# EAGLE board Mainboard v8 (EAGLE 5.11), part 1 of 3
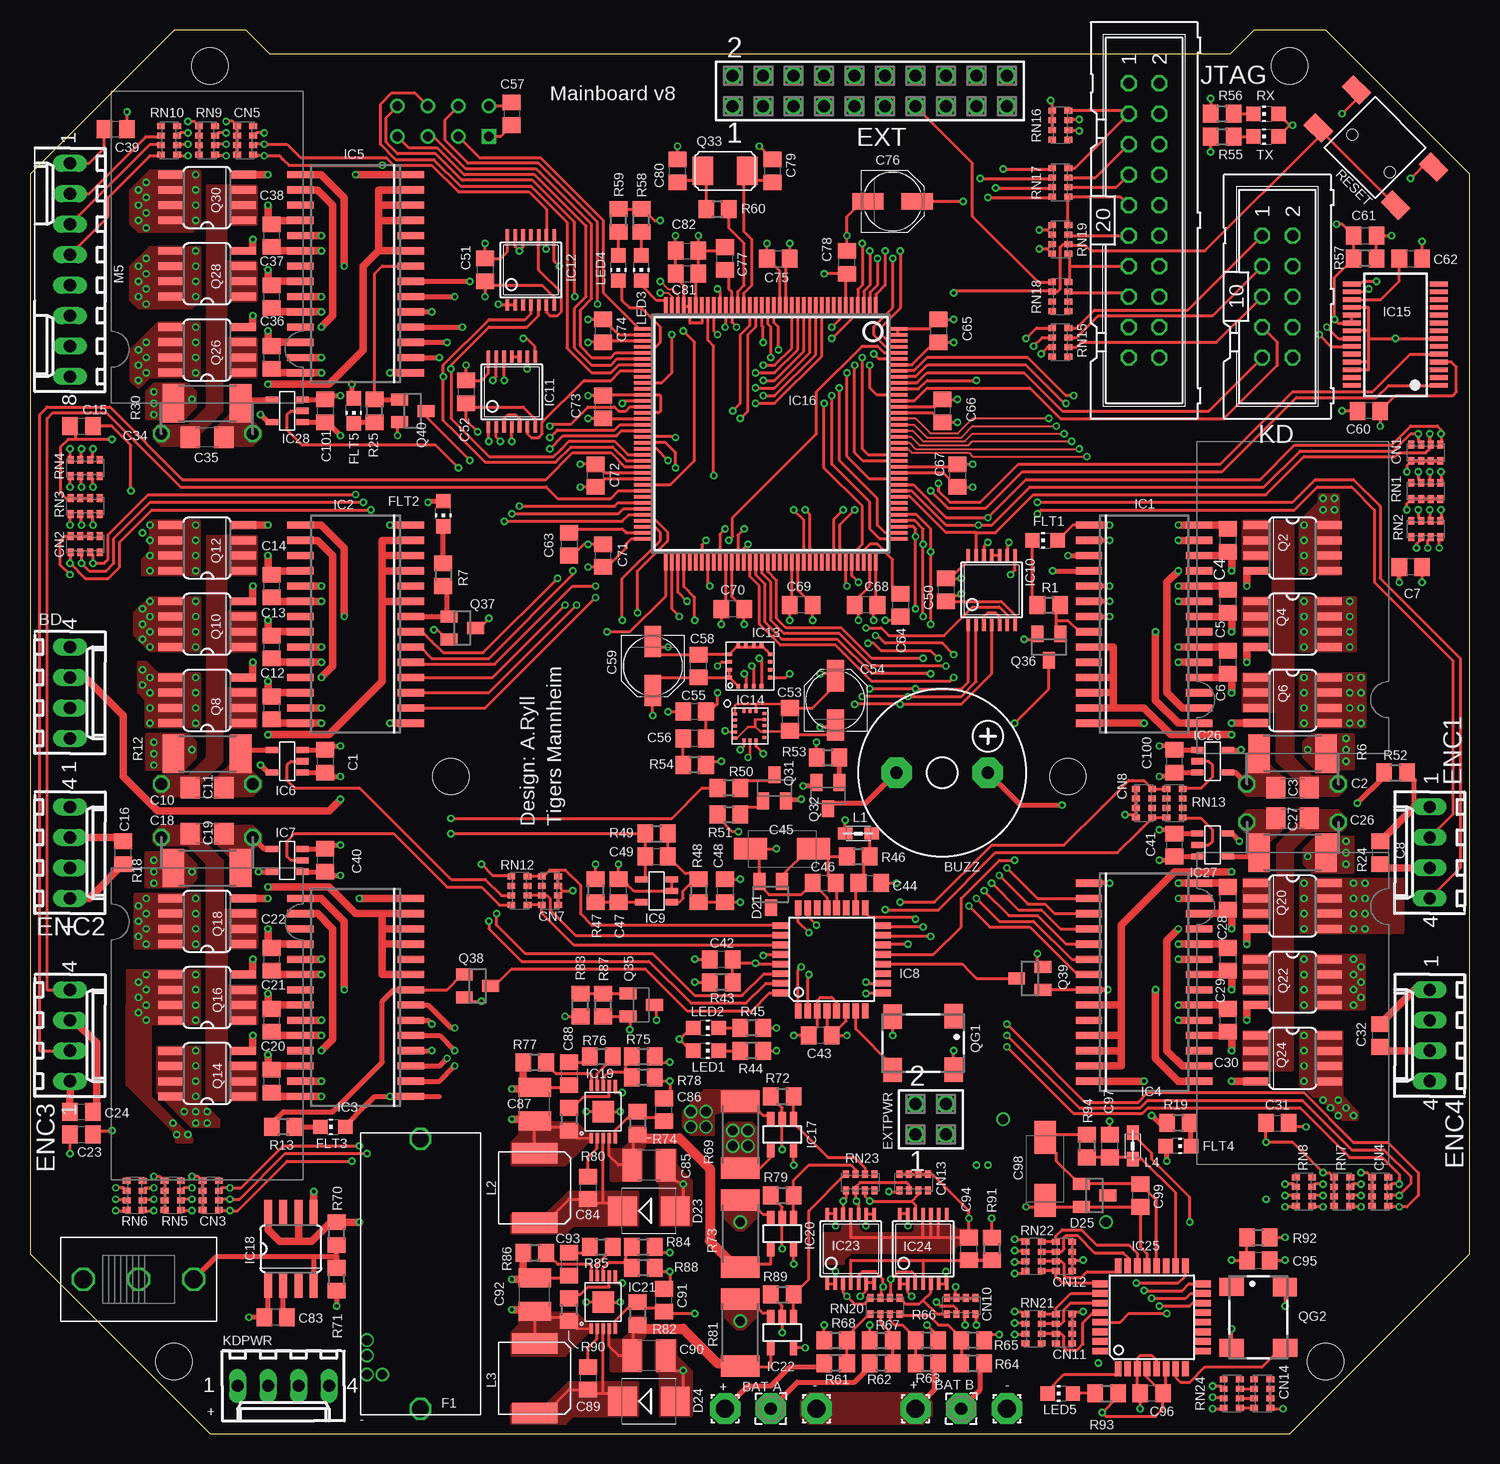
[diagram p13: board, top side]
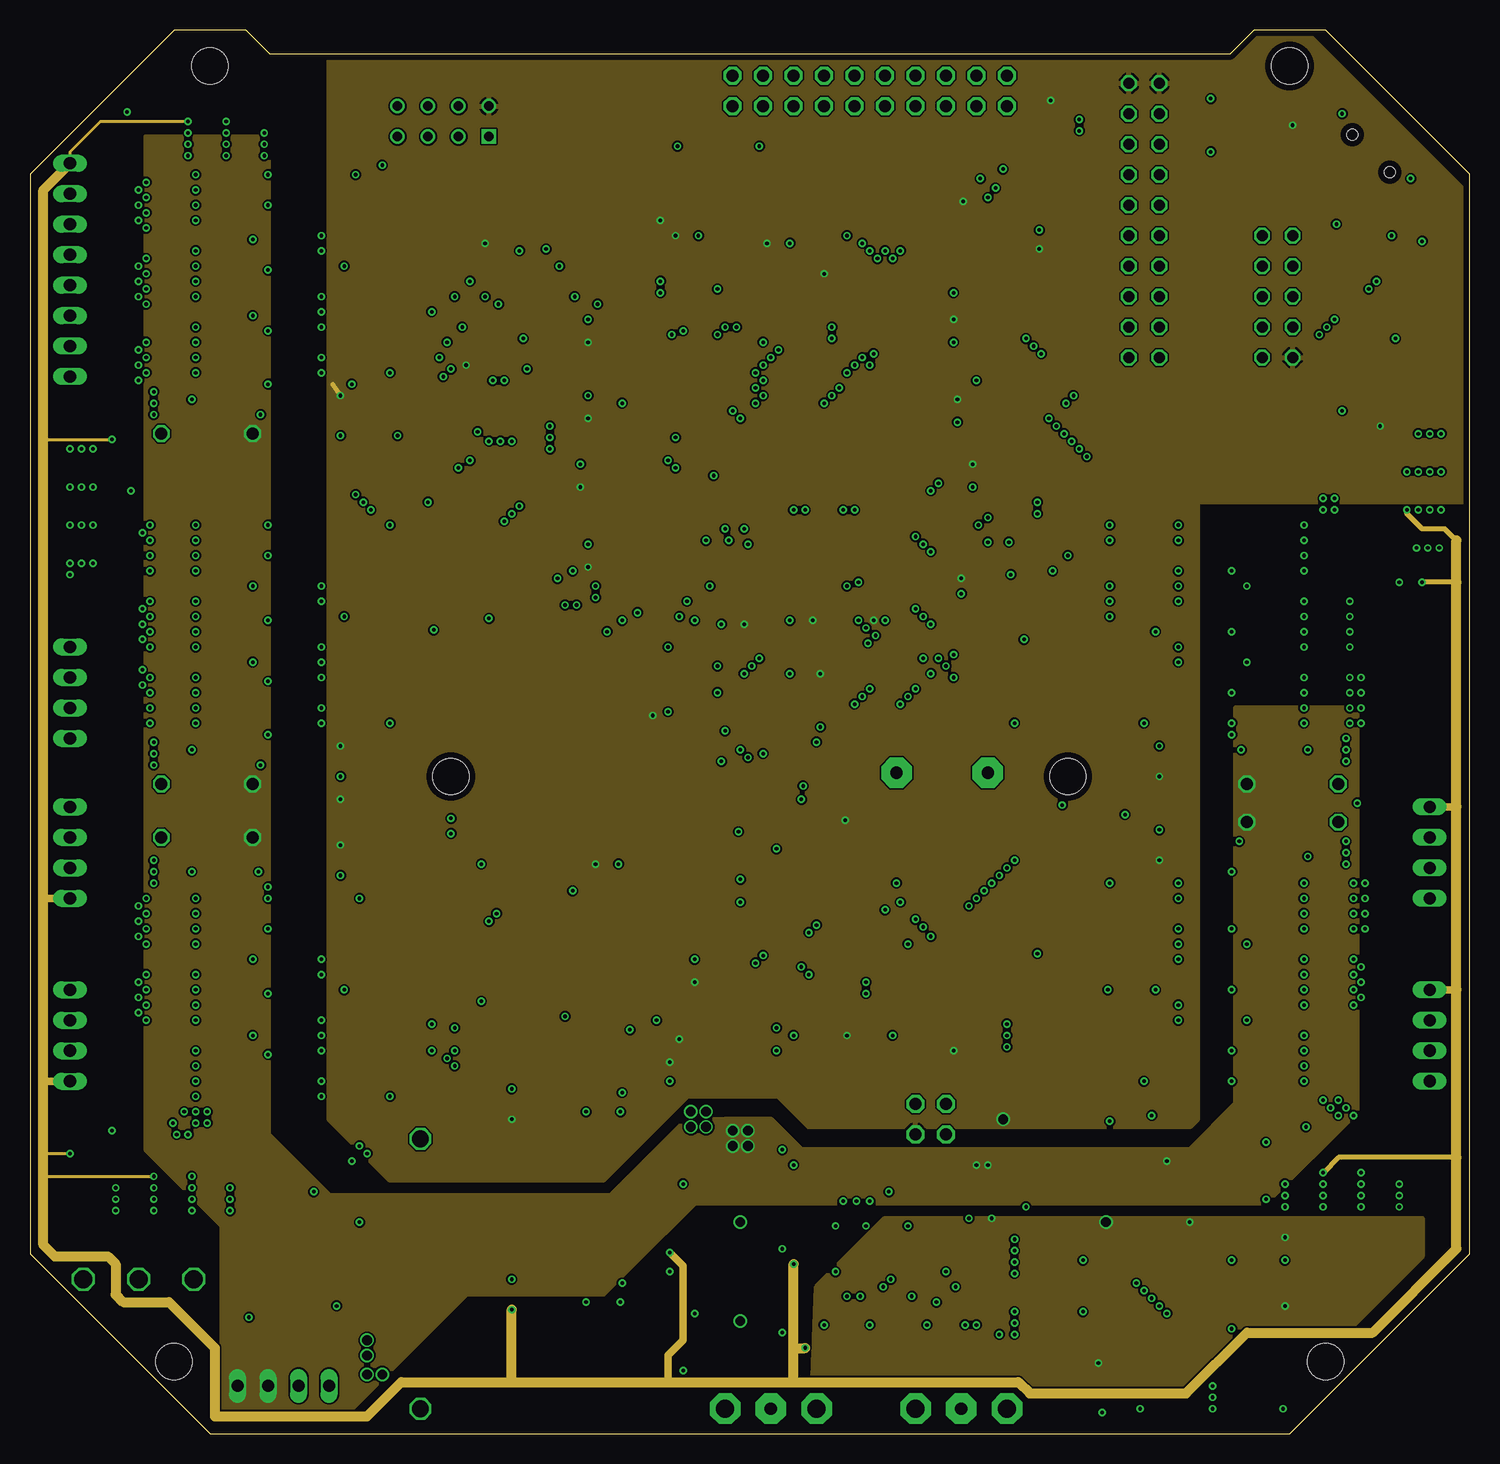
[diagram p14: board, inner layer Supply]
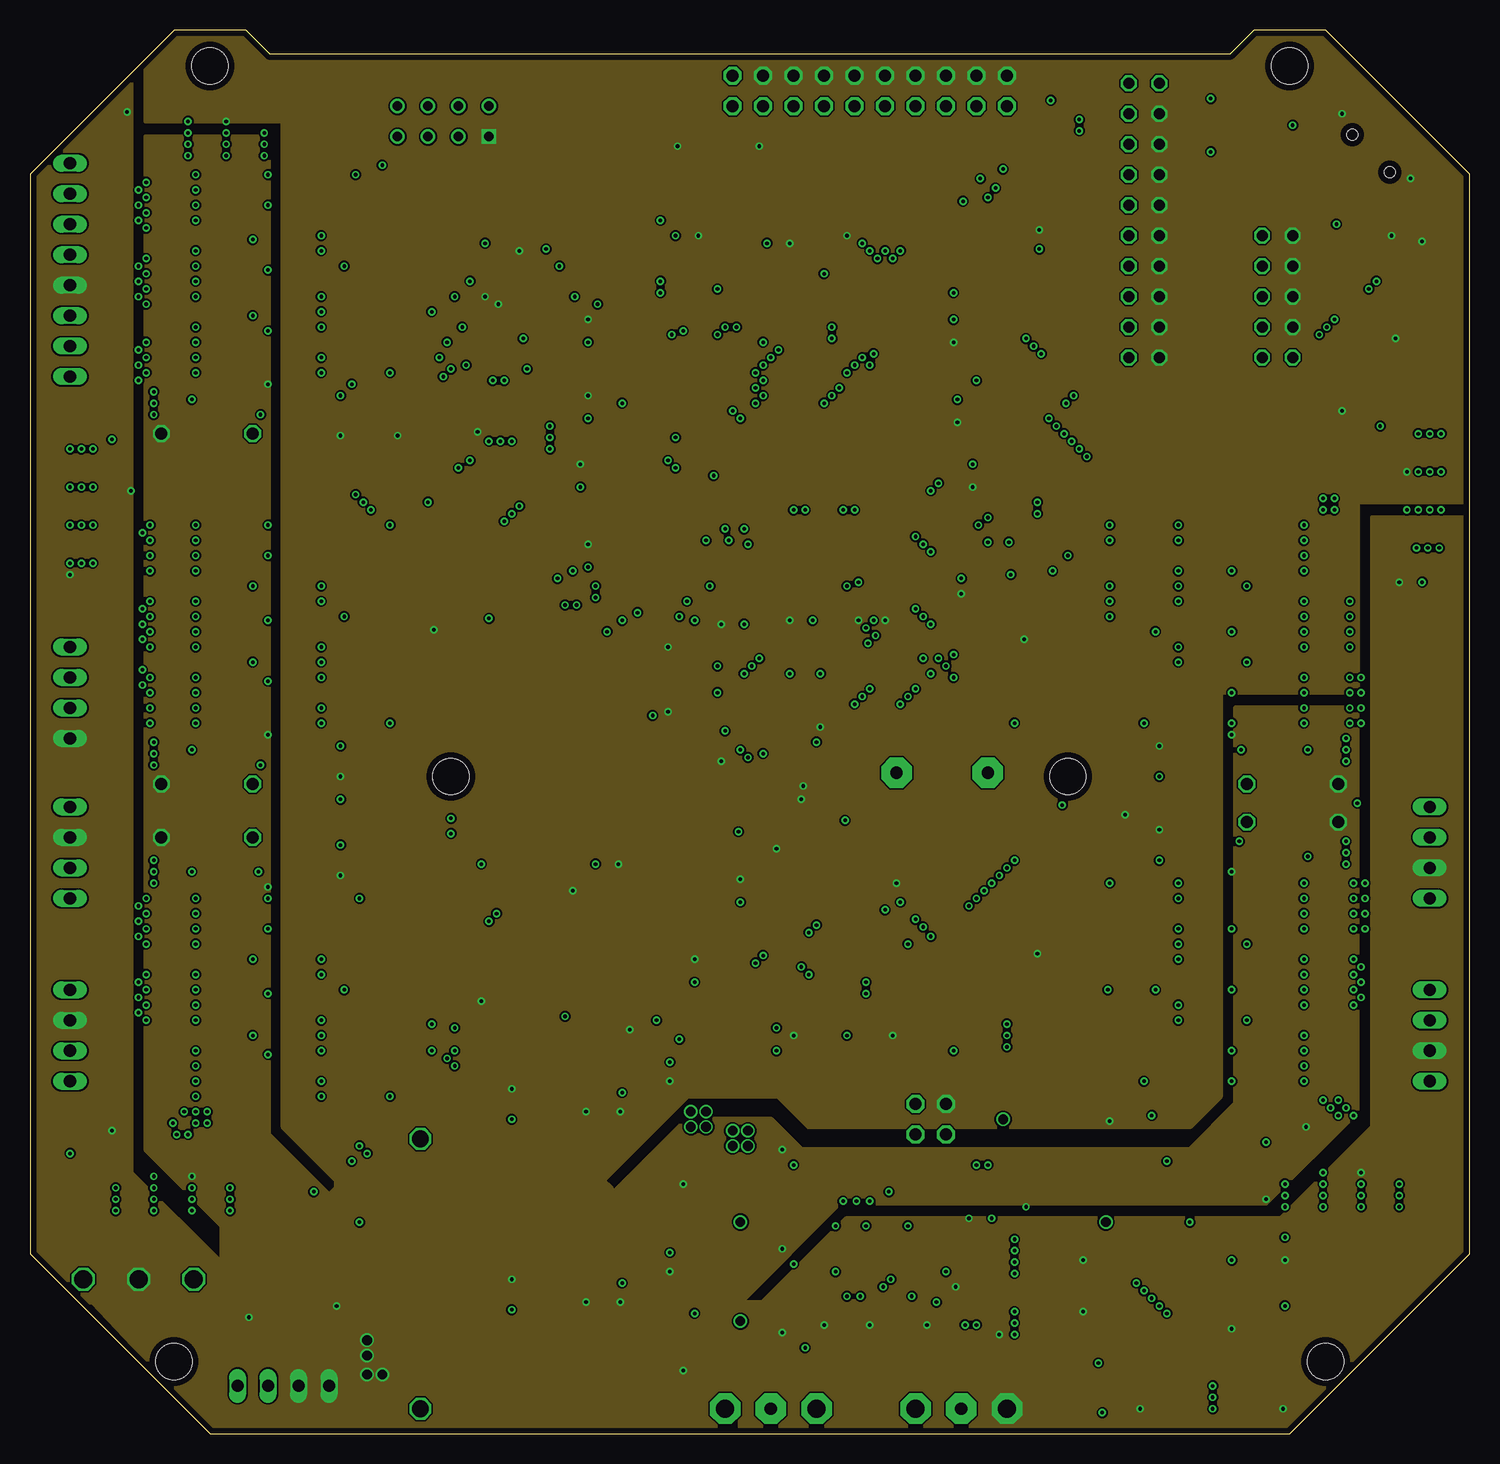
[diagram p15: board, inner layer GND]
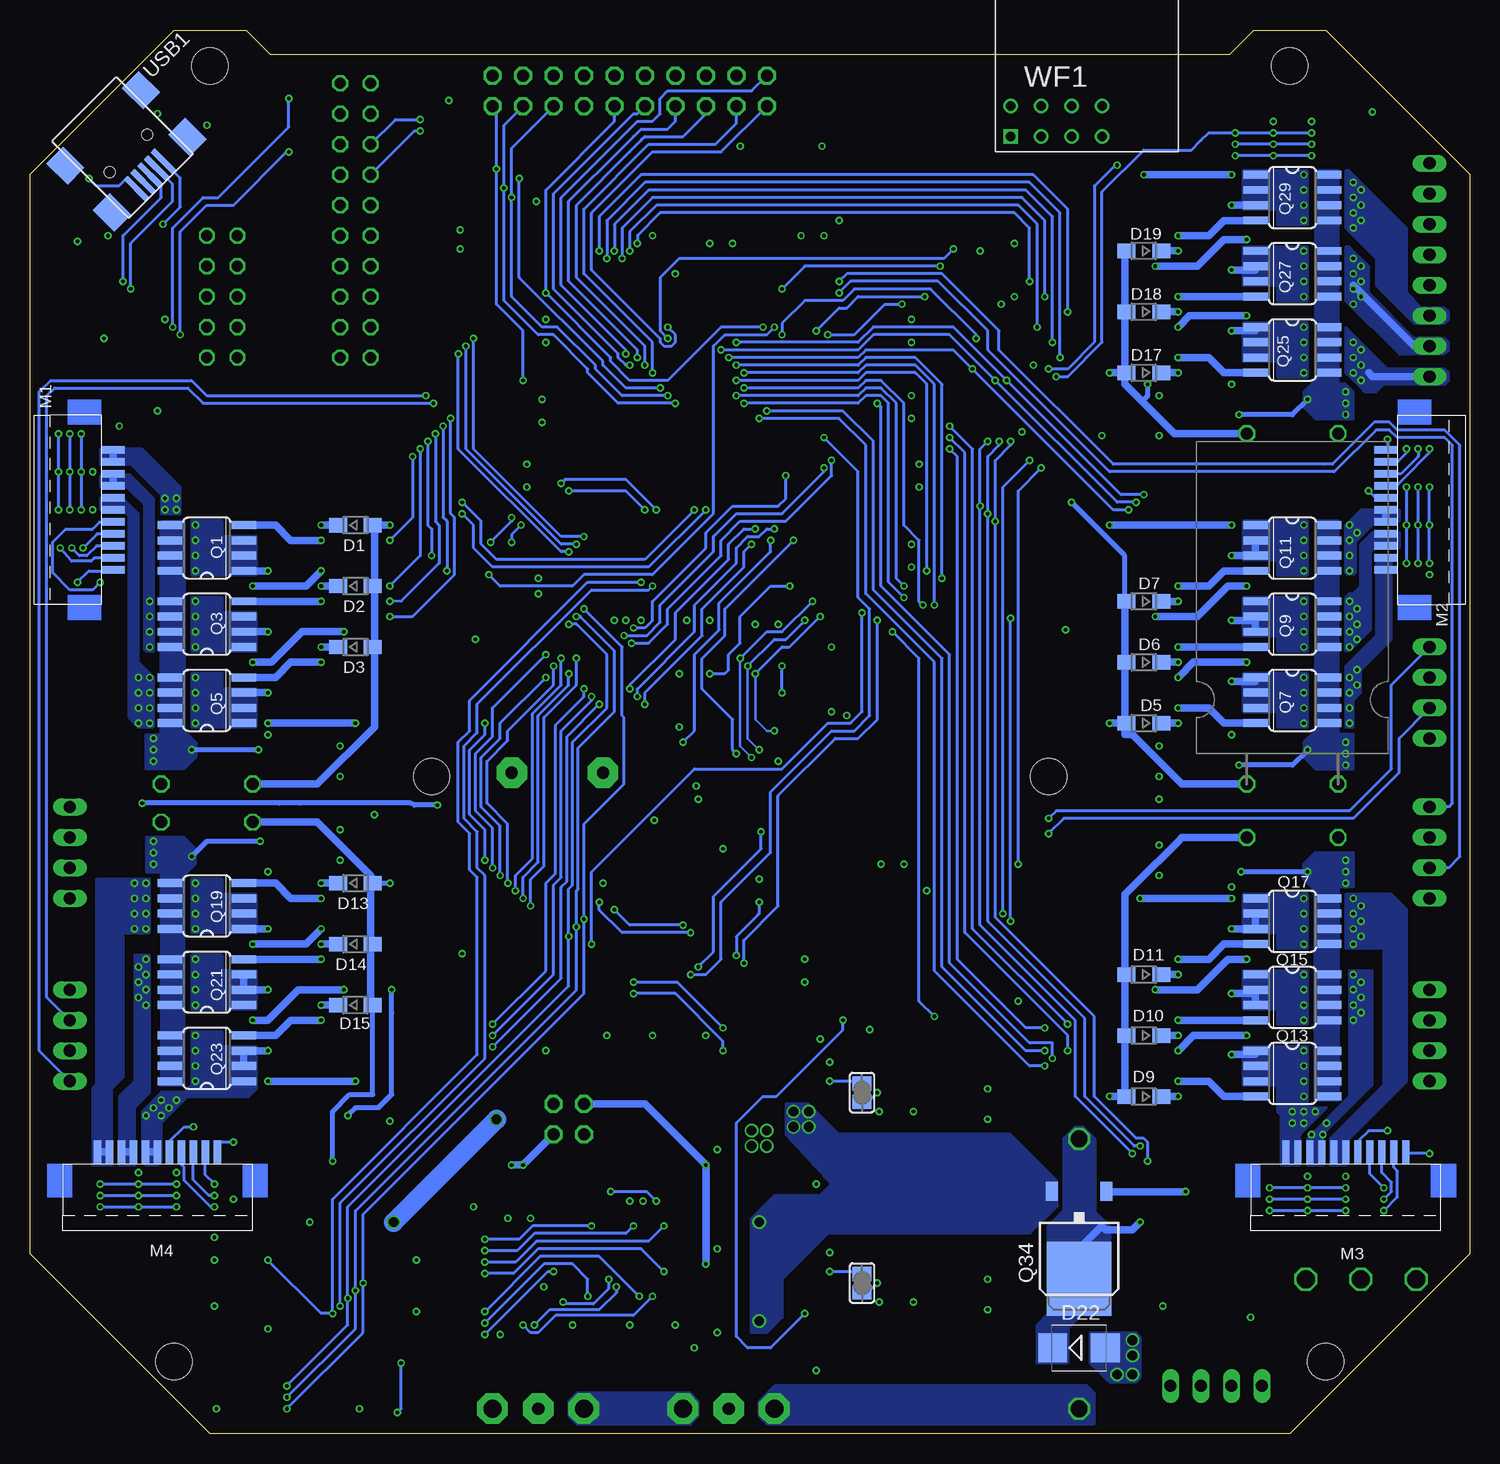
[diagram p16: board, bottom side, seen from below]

Size 120 x 117 mm. Coordinates in mm from the lower left corner, seen from the top.
Outline: 15,0 105,0 120,15 120,105 108,117 102,117 100,115 20,115 18,117 12,117 0,105 0,15 15,0
Copper layers (1+2*15+16): Top 0.035mm / dielectric 1.5mm / Supply 0.035mm / dielectric 0.15mm / GND 0.035mm / dielectric 0.2mm / Bottom 0.035mm
Design rules "PCB-POOL *": minimum track width 6mil, minimum drill 12mil, track to track 6mil, track to pad 6mil, pad to pad 6mil, via to via 6mil, smd to smd 6mil, copper to edge 20mil, drill to drill 8mil, minimum pad ring 8mil, minimum via ring 6mil, stop-mask expansion 3mil, vias tented up to drill 0mil, thermal gap 8mil
Net classes: 0 default: width 0.152 mm, clearance 0.152 mm
Holes 3 mm at 15,114 12,6 105,114 108,6 35.09,54.77 86.52,54.77
tKeepout: area 12,111 to 18,117; area 102,111 to 108,117; area 105,3 to 111,9; area 9,3 to 15,9; area 31.9,51.6 to 38.3,57.9; area 83.3,51.6 to 89.7,57.9
bKeepout: area 121.5,93.5 to 128.5,100.5

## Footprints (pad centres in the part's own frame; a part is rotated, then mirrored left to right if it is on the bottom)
2,54/1,0 = drill 1.016 pad 2.54 octagon: 1 0,0
2,54/1,5 = drill 1.5 pad 2.54 octagon: P$1 0,0
6410-04 = drill 1.016 long: 1 3.81,0; 2 1.27,0; 3 -1.27,0; 4 -3.81,0
F/CM12P = drill 1.016 pad 2.54 octagon: + 3.81,0; - -3.81,0
C0805 = smd 1.3 x 1.5: 1 -0.95,0; 2 0.95,0
C25-16L = drill 1 octagon: A -3.81,-2.54; B 3.81,-2.54
C1206 = smd 1.6 x 1.8: 1 -1.4,0; 2 1.4,0
C/6032-28W = smd 2.75 x 1.8: + 2.625,0; - -2.625,0
PANASONIC_C = smd 2.6 x 1.4: + 2.05,0; - -2.05,0
C1210 = smd 1.6 x 2.7: 1 -1.4,0; 2 1.4,0
CAY16 = smd 0.5 x 0.65: 1 -1.2,-0.675; 2 -0.4,-0.675; 3 0.4,-0.675; 4 1.2,-0.675; 5 1.2,0.675; 6 0.4,0.675; 7 -0.4,0.675; 8 -1.2,0.675
SOD323-W = smd 1.5 x 1.2: A 1.45,0; C -1.45,0
SOT23 = smd 1 x 1.4: 1 -0.95,-1.1; 2 0.95,-1.1; 3 0,1.1
SMB = smd 2.4 x 2.4: A 2.2,0; C -2.2,0
SSW-110-02-S-D = drill 1 pad 1.5 octagon: 1 -11.43,-1.27; 2 -11.43,1.27; 3 -8.89,-1.27; 4 -8.89,1.27; 5 -6.35,-1.27; 6 -6.35,1.27; 7 -3.81,-1.27; 8 -3.81,1.27; 9 -1.27,-1.27; 10 -1.27,1.27; 11 1.27,-1.27; 12 1.27,1.27; 13 3.81,-1.27; 14 3.81,1.27; 15 6.35,-1.27; 16 6.35,1.27; 17 8.89,-1.27; 18 8.89,1.27; 19 11.43,-1.27; 20 11.43,1.27
SSW-102-02-S-D = drill 1 pad 1.5 octagon: 1 -1.27,-1.27; 2 -1.27,1.27; 3 1.27,-1.27; 4 1.27,1.27
FUSE20X5-2 = drill 1.4 octagon: P$1 0,0; P$2 22.5,0
CHIP-LED0805 = smd 1.2 x 1.2: A 0,-1.05; C 0,1.05
SO28W = smd 0.6 x 2.2: 1 -8.255,-4.6; 2 -6.985,-4.6; 3 -5.715,-4.6; 4 -4.445,-4.6; 5 -3.175,-4.6; 6 -1.905,-4.6; 7 -0.635,-4.6; 8 0.635,-4.6; 9 1.905,-4.6; 10 3.175,-4.6; 11 4.445,-4.6; 12 5.715,-4.6; 13 6.985,-4.6; 14 8.255,-4.6; 15 8.255,4.6; 16 6.985,4.6; 17 5.715,4.6; 18 4.445,4.6; 19 3.175,4.6; 20 1.905,4.6; 21 0.635,4.6; 22 -0.635,4.6; 23 -1.905,4.6; 24 -3.175,4.6; 25 -4.445,4.6; 26 -5.715,4.6; 27 -6.985,4.6; 28 -8.255,4.6
SOT23-5 = smd 1.016 x 0.508: 1 -1.27,0.953; 2 -1.27,0; 3 -1.27,-0.953; 4 1.27,-0.953; 5 1.27,0.953
TQFP32-08 = smd 1.27 x 0.559: 1 -4.293,2.8; 2 -4.293,2; 3 -4.293,1.2; 4 -4.293,0.4; 5 -4.293,-0.4; 6 -4.293,-1.2; 7 -4.293,-2; 8 -4.293,-2.8; 17 4.293,-2.8; 18 4.293,-2; 19 4.293,-1.2; 20 4.293,-0.4; 21 4.293,0.4; 22 4.293,1.2; 23 4.293,2; 24 4.293,2.8 | smd 0.559 x 1.27: 9 -2.8,-4.293; 10 -2,-4.293; 11 -1.2,-4.293; 12 -0.4,-4.293; 13 0.4,-4.293; 14 1.2,-4.293; 15 2,-4.293; 16 2.8,-4.293; 25 2.8,4.293; 26 2,4.293; 27 1.2,4.293; 28 0.4,4.293; 29 -0.4,4.293; 30 -1.2,4.293; 31 -2,4.293; 32 -2.8,4.293
TSSOP14 = smd 0.305 x 0.991: 1 -1.95,-2.918; 2 -1.3,-2.918; 3 -0.65,-2.918; 4 0,-2.918; 5 0.65,-2.918; 6 1.3,-2.918; 7 1.95,-2.918; 8 1.95,2.918; 9 1.3,2.918; 10 0.65,2.918; 11 0,2.918; 12 -0.65,2.918; 13 -1.3,2.918; 14 -1.95,2.918
LGA16L = smd 0.4 x 0.3: 1 -1.7,0.975; 2 -1.7,0.325; 3 -1.7,-0.325; 4 -1.7,-0.975; 9 1.7,-0.975; 10 1.7,-0.325; 11 1.7,0.325; 12 1.7,0.975 | smd 0.3 x 0.4: 5 -0.975,-1.7; 6 -0.325,-1.7; 7 0.325,-1.7; 8 0.975,-1.7; 13 0.975,1.7; 14 0.325,1.7; 15 -0.325,1.7; 16 -0.975,1.7
LGA16 = smd 0.35 x 0.25: 1 -1.225,1; 2 -1.225,0.5; 3 -1.225,0; 4 -1.225,-0.5; 5 -1.225,-1; 9 1.225,-0.995; 10 1.225,-0.495; 11 1.225,0.005; 12 1.225,0.505; 13 1.225,1.005 | smd 0.25 x 0.35: 6 -0.5,-1.225; 7 0,-1.225; 8 0.5,-1.225; 14 0.5,1.225; 15 0,1.225; 16 -0.5,1.225
SSOP28 = smd 0.4 x 1.5: 1 -4.225,-3.625; 2 -3.575,-3.625; 3 -2.925,-3.625; 4 -2.275,-3.625; 5 -1.625,-3.625; 6 -0.975,-3.625; 7 -0.325,-3.625; 8 0.325,-3.625; 9 0.975,-3.625; 10 1.625,-3.625; 11 2.275,-3.625; 12 2.925,-3.625; 13 3.575,-3.625; 14 4.225,-3.625; 15 4.225,3.625; 16 3.575,3.625; 17 2.925,3.625; 18 2.275,3.625; 19 1.625,3.625; 20 0.975,3.625; 21 0.325,3.625; 22 -0.325,3.625; 23 -0.975,3.625; 24 -1.625,3.625; 25 -2.275,3.625; 26 -2.925,3.625; 27 -3.575,3.625; 28 -4.225,3.625
SQFP-S-20X20-144 = smd 0.3 x 1.6: 1 -8.75,-10.6; 2 -8.25,-10.6; 3 -7.75,-10.6; 4 -7.25,-10.6; 5 -6.75,-10.6; 6 -6.25,-10.6; 7 -5.75,-10.6; 8 -5.25,-10.6; 9 -4.75,-10.6; 10 -4.25,-10.6; 11 -3.75,-10.6; 12 -3.25,-10.6; 13 -2.75,-10.6; 14 -2.25,-10.6; 15 -1.75,-10.6; 16 -1.25,-10.6; 17 -0.75,-10.6; 18 -0.25,-10.6; 19 0.25,-10.6; 20 0.75,-10.6; 21 1.25,-10.6; 22 1.75,-10.6; 23 2.25,-10.6; 24 2.75,-10.6; 25 3.25,-10.6; 26 3.75,-10.6; 27 4.25,-10.6; 28 4.75,-10.6; 29 5.25,-10.6; 30 5.75,-10.6; 31 6.25,-10.6; 32 6.75,-10.6; 33 7.25,-10.6; 34 7.75,-10.6; 35 8.25,-10.6; 36 8.75,-10.6; 73 8.75,10.6; 74 8.25,10.6; 75 7.75,10.6; 76 7.25,10.6; 77 6.75,10.6; 78 6.25,10.6; 79 5.75,10.6; 80 5.25,10.6; 81 4.75,10.6; 82 4.25,10.6; 83 3.75,10.6; 84 3.25,10.6; 85 2.75,10.6; 86 2.25,10.6; 87 1.75,10.6; 88 1.25,10.6; 89 0.75,10.6; 90 0.25,10.6; 91 -0.25,10.6; 92 -0.75,10.6; 93 -1.25,10.6; 94 -1.75,10.6; 95 -2.25,10.6; 96 -2.75,10.6; 97 -3.25,10.6; 98 -3.75,10.6; 99 -4.25,10.6; 100 -4.75,10.6; 101 -5.25,10.6; 102 -5.75,10.6; 103 -6.25,10.6; 104 -6.75,10.6; 105 -7.25,10.6; 106 -7.75,10.6; 107 -8.25,10.6; 108 -8.75,10.6 | smd 1.6 x 0.3: 37 10.6,-8.75; 38 10.6,-8.25; 39 10.6,-7.75; 40 10.6,-7.25; 41 10.6,-6.75; 42 10.6,-6.25; 43 10.6,-5.75; 44 10.6,-5.25; 45 10.6,-4.75; 46 10.6,-4.25; 47 10.6,-3.75; 48 10.6,-3.25; 49 10.6,-2.75; 50 10.6,-2.25; 51 10.6,-1.75; 52 10.6,-1.25; 53 10.6,-0.75; 54 10.6,-0.25; 55 10.6,0.25; 56 10.6,0.75; 57 10.6,1.25; 58 10.6,1.75; 59 10.6,2.25; 60 10.6,2.75; 61 10.6,3.25; 62 10.6,3.75; 63 10.6,4.25; 64 10.6,4.75; 65 10.6,5.25; 66 10.6,5.75; 67 10.6,6.25; 68 10.6,6.75; 69 10.6,7.25; 70 10.6,7.75; 71 10.6,8.25; 72 10.6,8.75; 109 -10.6,8.75; 110 -10.6,8.25; 111 -10.6,7.75; 112 -10.6,7.25; 113 -10.6,6.75; 114 -10.6,6.25; 115 -10.6,5.75; 116 -10.6,5.25; 117 -10.6,4.75; 118 -10.6,4.25; 119 -10.6,3.75; 120 -10.6,3.25; 121 -10.6,2.75; 122 -10.6,2.25; 123 -10.6,1.75; 124 -10.6,1.25; 125 -10.6,0.75; 126 -10.6,0.25; 127 -10.6,-0.25; 128 -10.6,-0.75; 129 -10.6,-1.25; 130 -10.6,-1.75; 131 -10.6,-2.25; 132 -10.6,-2.75; 133 -10.6,-3.25; 134 -10.6,-3.75; 135 -10.6,-4.25; 136 -10.6,-4.75; 137 -10.6,-5.25; 138 -10.6,-5.75; 139 -10.6,-6.25; 140 -10.6,-6.75; 141 -10.6,-7.25; 142 -10.6,-7.75; 143 -10.6,-8.25; 144 -10.6,-8.75
SOT23-5' = smd 0.6 x 1.2: 1 -0.95,-1.306; 2 0,-1.306; 3 0.95,-1.306; 4 0.95,1.306; 5 -0.95,1.306
SOIC8 = smd 0.66 x 2.032: 1 -1.905,-3.073; 2 -0.635,-3.073; 3 0.635,-3.073; 4 1.905,-3.073; 5 1.905,3.073; 6 0.635,3.073; 7 -0.635,3.073; 8 -1.905,3.073
MSOP10 = smd 0.9 x 0.3: 1 -2.2,1; 2 -2.2,0.5; 3 -2.2,0; 4 -2.2,-0.5; 5 -2.2,-1; 6 2.2,-1; 7 2.2,-0.5; 8 2.2,0; 9 2.2,0.5; 10 2.2,1 | smd 1.778 x 1.778: 11 0,0
ML20 = drill 0.914 octagon: 1 -11.43,-1.27; 2 -11.43,1.27; 3 -8.89,-1.27; 4 -8.89,1.27; 5 -6.35,-1.27; 6 -6.35,1.27; 7 -3.81,-1.27; 8 -3.81,1.27; 9 -1.27,-1.27; 10 -1.27,1.27; 11 1.27,-1.27; 12 1.27,1.27; 13 3.81,-1.27; 14 3.81,1.27; 15 6.35,-1.27; 16 6.35,1.27; 17 8.89,-1.27; 18 8.89,1.27; 19 11.43,-1.27; 20 11.43,1.27
ML10 = drill 0.914 octagon: 1 -5.08,-1.27; 2 -5.08,1.27; 3 -2.54,-1.27; 4 -2.54,1.27; 5 0,-1.27; 6 0,1.27; 7 2.54,-1.27; 8 2.54,1.27; 9 5.08,-1.27; 10 5.08,1.27
0805 = smd 1.2 x 1: 1 -1.1,0; 2 1.1,0
L-ELL6 = smd 1.7 x 3.8: P$1 -2.9,0; P$2 2.9,0
MOLEX11 = smd 0.6 x 1.9: 1 5,3; 2 4,3; 3 3,3; 4 2,3; 5 1,3; 6 0,3; 7 -1,3; 8 -2,3; 9 -3,3; 10 -4,3; 11 -5,3
6410-08 = drill 1.016 long: 1 8.89,0; 2 6.35,0; 3 3.81,0; 4 1.27,0; 5 -1.27,0; 6 -3.81,0; 7 -6.35,0; 8 -8.89,0
SOT23-BEC = smd 1 x 1.4: B -0.95,-1.1; C 0,1.1; E 0.95,-1.1
CRYSTAL-7A = smd 1.7 x 2.4: 1 -1.85,0; 2 1.85,0
D-PAK_TO252AA = smd 1 x 1.6: 1 -2.28,-4.8; 3 2.28,-4.8 | smd 5.4 x 6.2: 4 0,2.5
SM77H = smd 1.524 x 2.032: 1 -2.545,-2.232; 2 2.535,-2.212; 3 2.545,2.232; 4 -2.535,2.212
R0805 = smd 1.3 x 1.5: 1 -0.95,0; 2 0.95,0
R2512 = smd 1.8 x 3.2: 1 -2.8,0; 2 2.8,0
BUTTON4 = smd 1.4 x 2.1: 1 4.5,9.1; 2 4.5,0; 3 0,9.1; 4 0,0
SJ = smd 1.168 x 1.6: 1 -0.762,0; 2 0.762,0
SW-KNITTER = drill 1.5 octagon: 1 -4.6,0; 2 0,0; 3 4.6,0
USB-BMINI = smd 2.5 x 0.5: 1 0,1.6; 2 0,0.8; 3 0,0; 4 0,-0.8; 5 0,-1.6 | smd 2.5 x 2: P$6 0,4.45; P$7 0,-4.45; P$8 -5.5,4.45; P$9 -5.5,-4.45 | hole 0.9: -2.5,2.2; -2.5,-2.2
NRF24L01MOD = drill 0.8 square: 1 0,0 | drill 0.8 round: 2 0,2.54; 3 2.54,0; 4 2.54,2.54; 5 5.08,0; 6 5.08,2.54; 7 7.62,0; 8 7.62,2.54

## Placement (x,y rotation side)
BAT1#  [2,54/1,0]  61.75,2.06 0 top
BAT1+  [2,54/1,5]  57.94,2.06 0 top
BAT1-  [2,54/1,5]  65.56,2.06 0 top
BAT2#  [2,54/1,0]  77.63,2.06 0 top
BAT2+  [2,54/1,5]  73.82,2.06 0 top
BAT2-  [2,54/1,5]  81.44,2.06 0 top
BD  22-27-2041-04  [6410-04]  3.34,61.75 270 top
BUZZ  F/CM12P  [F/CM12P]  76.04,55.09 0 top
C1  100n  [C0805]  24.61,56.04 270 top
C2  3300u/25V  [C25-16L]  105.25,56.67 0 top
C3  22u  [C1206]  105.25,53.82 0 top
C4  10u  [C0805]  99.86,74.45 270 top
C5  10u  [C0805]  99.86,69.38 270 top
C6  10u  [C0805]  99.86,64.3 270 top
C7  100n  [C0805]  115.09,72.23 180 top
C8  100n  [C0805]  112.56,48.42 270 top
C10  3300u/25V  [C25-16L]  14.77,56.67 0 bottom
C11  22u  [C1206]  14.77,53.82 180 top
C12  10u  [C0805]  20.16,60.48 90 top
C13  10u  [C0805]  20.16,65.56 90 top
C14  10u  [C0805]  20.16,70.64 90 top
C15  100n  [C0805]  4.29,83.98 0 top
C16  100n  [C0805]  7.78,48.42 90 top
C18  3300u/25V  [C25-16L]  14.77,47.15 180 top
C19  22u  [C1206]  14.77,50.01 180 top
C20  10u  [C0805]  20.16,29.37 90 top
C21  10u  [C0805]  20.16,34.45 90 top
C22  10u  [C0805]  20.16,39.53 90 top
C23  100n  [C0805]  4.29,24.92 0 top
C24  100n  [C0805]  4.29,26.83 0 top
C26  3300u/25V  [C25-16L]  105.25,48.42 180 top
C27  22u  [C1206]  105.25,51.28 0 top
C28  10u  [C0805]  99.86,44.61 270 top
C29  10u  [C0805]  99.86,39.53 270 top
C30  10u  [C0805]  99.86,34.45 270 top
C31  100n  [C0805]  103.98,25.88 0 top
C32  100n  [C0805]  112.56,33.18 270 top
C34  3300u/25V  [C25-16L]  14.77,85.89 0 top
C35  22u  [C1206]  14.77,83.03 180 top
C36  10u  [C0805]  20.16,89.69 90 top
C37  10u  [C0805]  20.16,94.78 90 top
C38  10u  [C0805]  20.16,99.86 90 top
C39  100n  [C0805]  7.14,108.75 0 top
C40  100n  [C0805]  24.61,47.78 270 top
C41  100n  [C0805]  95.41,49.05 90 top
C42  100n  [C0805]  57.63,39.53 180 top
C43  100n  [C0805]  65.88,33.18 180 top
C44  100n  [C0805]  70.01,45.88 0 top
C45  10u  [C/6032-28W]  62.71,48.74 0 top
C46  100n  [C0805]  66.2,45.88 180 top
C47  10u  [C0805]  49.05,45.24 90 top
C48  100n  [C0805]  57.94,45.24 270 top
C49  47p  [C0805]  52.23,48.1 0 top
C50  100n  [C0805]  76.36,70.33 270 top
C51  100n  [C0805]  37.94,97 270 top
C52  100n  [C0805]  36.35,86.84 270 top
C53  100n  [C0805]  63.34,59.53 270 top
C54  10u  [PANASONIC_C]  67.15,61.12 90 top
C55  10n  [C0805]  55.41,60.17 180 top
C56  470n  [C0805]  55.41,57.94 180 top
C57  100n  [C0805]  40.16,110.02 270 top
C58  100n  [C0805]  55.72,63.98 90 top
C59  10u  [PANASONIC_C]  51.91,63.98 270 top
C60  100n  [C0805]  111.6,85.25 180 top
C61  10u  [C0805]  111.28,99.86 0 top
C62  100n  [C0805]  115.09,97.95 0 top
C63  2u2  [C0805]  44.93,74.14 270 top
C64  2u2  [C0805]  72.55,69.06 270 top
C65  100n  [C0805]  75.72,91.92 270 top
C66  100n  [C0805]  76.04,85.25 270 top
C67  100n  [C0805]  77.31,79.85 270 top
C68  100n  [C0805]  69.69,69.06 180 top
C69  100n  [C0805]  64.3,69.06 180 top
C70  100n  [C0805]  58.58,68.74 180 top
C71  100n  [C0805]  47.78,73.19 90 top
C72  100n  [C0805]  47.15,79.85 90 top
C73  100n  [C0805]  47.78,85.57 90 top
C74  100n  [C0805]  47.78,91.92 90 top
C75  100n  [C0805]  62.39,97.95 0 top
C76  10u  [PANASONIC_C]  71.92,102.71 0 top
C77  100n  [C0805]  57.94,97.95 90 top
C78  100n  [C0805]  68.11,97.63 90 top
C79  18p  [C0805]  61.91,105.25 90 top
C80  18p  [C0805]  53.98,105.25 90 top
C81  10u  [C0805]  54.77,96.68 0 top
C82  100n  [C0805]  54.77,98.58 0 top
C83  100n  [C0805]  20.48,9.68 180 top
C84  470n  [C0805]  46.52,20.48 270 top
C85  10u  [C1210]  51.59,22.38 0 top
C86  100n  [C0805]  52.87,26.99 90 top
C87  47u  [C1210]  42.07,27.47 90 top
C88  470p  [C0805]  44.93,30.01 270 top
C89  470n  [C0805]  46.52,4.61 270 top
C90  10u  [C1210]  51.59,6.51 0 top
C91  100n  [C0805]  52.87,11.11 90 top
C92  47u  [C1210]  42.07,11.59 90 top
C93  470p  [C0805]  44.93,14.13 270 top
C94  10u  [C0805]  78.27,15.4 90 top
C95  100n  [C0805]  102.39,14.45 0 top
C96  100n  [C0805]  93.5,3.34 180 top
C97  100n  [C0805]  90.01,23.97 90 top
C98  10u  [C/6032-28W]  84.61,22.07 90 top
C99  100n  [C0805]  92.55,19.84 270 top
C100  100n  [C0805]  95.41,56.04 90 top
C101  100n  [C0805]  24.61,85.25 270 top
CN1  1n  [CAY16]  116.36,81.76 180 top
CN2  1n  [CAY16]  4.61,74.14 0 top
CN3  1n  [CAY16]  15.08,19.84 90 top
CN4  1n  [CAY16]  112.56,20.16 90 top
CN5  1n  [CAY16]  17.94,107.79 90 top
CN7  NA  [CAY16]  43.34,45.24 270 top
CN8  NA  [CAY16]  92.87,52.55 90 top
CN10  100n  [CAY16]  77.63,10.64 180 top
CN11  100n  [CAY16]  86.2,8.73 270 top
CN12  100n  [CAY16]  86.2,14.77 270 top
CN13  100n  [CAY16]  73.66,20.96 0 top
CN14  100p  [CAY16]  102.71,3.34 270 top
D1  BAT41  [SOD323-W]  92.87,75.72 0 bottom
D2  BAT41  [SOD323-W]  92.87,70.64 0 bottom
D3  BAT41  [SOD323-W]  92.87,65.56 0 bottom
D5  BAT41  [SOD323-W]  27.15,59.22 180 bottom
D6  BAT41  [SOD323-W]  27.15,64.3 180 bottom
D7  BAT41  [SOD323-W]  27.15,69.38 180 bottom
D9  BAT41  [SOD323-W]  27.15,28.1 180 bottom
D10  BAT41  [SOD323-W]  27.15,33.18 180 bottom
D11  BAT41  [SOD323-W]  27.15,38.26 180 bottom
D13  BAT41  [SOD323-W]  92.87,45.88 0 bottom
D14  BAT41  [SOD323-W]  92.87,40.8 0 bottom
D15  BAT41  [SOD323-W]  92.87,35.72 0 bottom
D17  BAT41  [SOD323-W]  27.15,88.42 180 bottom
D18  BAT41  [SOD323-W]  27.15,93.5 180 bottom
D19  BAT41  [SOD323-W]  27.15,98.58 180 bottom
D21  LM4040-2.048  [SOT23]  61.75,44.93 180 top
D22  MBRS240  [SMB]  32.55,7.14 0 bottom
D23  MBRS240  [SMB]  51.59,18.57 0 top
D24  MBRS240  [SMB]  51.59,2.7 0 top
D25  LM4040-2.048  [SOT23]  88.74,19.84 270 top
ENC1  22-27-2041-04  [6410-04]  116.68,48.42 90 top
ENC2  22-27-2041-04  [6410-04]  3.34,48.42 270 top
ENC3  22-27-2041-04  [6410-04]  3.34,33.18 270 top
ENC4  22-27-2041-04  [6410-04]  116.68,33.18 90 top
EXT  SSW-110-01-T-D  [SSW-110-02-S-D]  70.01,111.92 0 top
EXTPWR  SSW-102-01-T-D  [SSW-102-02-S-D]  75.09,26.2 0 top
F1  [FUSE20X5-2]  32.55,2.06 90 top
FLT1  rd  [CHIP-LED0805]  84.61,74.45 90 top
FLT2  rd  [CHIP-LED0805]  34.45,76.68 180 top
FLT3  rd  [CHIP-LED0805]  25.24,25.56 90 top
FLT4  rd  [CHIP-LED0805]  95.73,23.97 270 top
FLT5  rd  [CHIP-LED0805]  26.99,85.25 180 top
IC1  IR2130S  [SO28W]  92.87,67.47 270 top
IC2  IR2130S  [SO28W]  27.15,67.47 90 top
IC3  IR2130S  [SO28W]  27.15,36.35 90 top
IC4  IR2130S  [SO28W]  92.87,37.62 270 top
IC5  IR2130S  [SO28W]  27.15,96.68 90 top
IC6  MAX4372_EUK  [SOT23-5]  21.43,56.04 180 top
IC7  MAX4372_EUK  [SOT23-5]  21.43,47.78 180 top
IC8  MEGA48/88/168-AU  [TQFP32-08]  66.83,39.53 90 top
IC9  AD8691  [SOT23-5]  52.23,45.24 180 top
IC10  7486PW  [TSSOP14]  80.17,70.33 0 top
IC11  7486PW  [TSSOP14]  40.16,86.84 0 top
IC12  7486PW  [TSSOP14]  41.75,97 0 top
IC13  L3G4200D  [LGA16L]  60,64 90 top
IC14  LIS3DH  [LGA16]  60,59 0 top
IC15  FT232RL  [SSOP28]  113.83,91.6 90 top
IC16  [SQFP-S-20X20-144]  61.75,83.34 180 top
IC17  INA139  [SOT23-5']  62.71,24.92 180 top
IC18  LT1910  [SOIC8]  21.75,15.4 0 top
IC19  LT3480  [MSOP10]  47.78,26.83 90 top
IC20  INA139  [SOT23-5']  62.71,16.67 180 top
IC21  LT3480  [MSOP10]  47.78,10.95 90 top
IC22  INA139  [SOT23-5']  62.71,8.41 180 top
IC23  AD8648  [TSSOP14]  68.42,15.4 0 top
IC24  AD8648  [TSSOP14]  74.45,15.4 0 top
IC25  MEGA48/88/168-AU  [TQFP32-08]  93.5,9.68 90 top
IC26  MAX4372_EUK  [SOT23-5]  98.58,56.04 0 top
IC27  MAX4372_EUK  [SOT23-5]  98.58,49.05 0 top
IC28  MAX4372_EUK  [SOT23-5]  21.43,85.25 180 top
JTAG  [ML20]  92.87,101.12 270 top
KD  [ML10]  103.98,94.78 270 top
KDPWR  MOLEX4  [6410-04]  21.11,3.97 180 top
L1  10u  [0805]  69.06,50.01 0 top
L2  6u8  [L-ELL6]  42.07,20.48 270 top
L3  6u8  [L-ELL6]  42.07,4.61 270 top
L4  10u  [0805]  91.92,23.97 270 top
LED1  rd  [CHIP-LED0805]  56.36,31.91 270 top
LED2  gr  [CHIP-LED0805]  56.36,33.81 270 top
LED3  rd  [CHIP-LED0805]  50.96,97.16 180 top
LED4  gr  [CHIP-LED0805]  49.05,97.16 180 top
LED5  gr  [CHIP-LED0805]  85.89,3.34 90 top
M1  [MOLEX11]  116.05,77 270 bottom
M2  [MOLEX11]  3.97,77 90 bottom
M3  [MOLEX11]  10.32,20.48 0 bottom
M4  [MOLEX11]  109.38,20.48 0 bottom
M5  MOLEX8  [6410-08]  3.34,97 90 top
Q1  FDS6670  [SOIC8]  105.25,73.82 90 bottom
Q2  FDS6670  [SOIC8]  105.25,73.82 270 top
Q3  FDS6670  [SOIC8]  105.25,67.47 90 bottom
Q4  FDS6670  [SOIC8]  105.25,67.47 270 top
Q5  FDS6670  [SOIC8]  105.25,61.12 90 bottom
Q6  FDS6670  [SOIC8]  105.25,61.12 270 top
Q7  FDS6670  [SOIC8]  14.77,61.12 270 bottom
Q8  FDS6670  [SOIC8]  14.77,61.12 90 top
Q9  FDS6670  [SOIC8]  14.77,67.47 270 bottom
Q10  FDS6670  [SOIC8]  14.77,67.47 90 top
Q11  FDS6670  [SOIC8]  14.77,73.82 270 bottom
Q12  FDS6670  [SOIC8]  14.77,73.82 90 top
Q13  FDS6670  [SOIC8]  14.77,30.01 270 bottom
Q14  FDS6670  [SOIC8]  14.77,30.01 90 top
Q15  FDS6670  [SOIC8]  14.77,36.35 270 bottom
Q16  FDS6670  [SOIC8]  14.77,36.35 90 top
Q17  FDS6670  [SOIC8]  14.77,42.7 270 bottom
Q18  FDS6670  [SOIC8]  14.77,42.7 90 top
Q19  FDS6670  [SOIC8]  105.25,43.98 90 bottom
Q20  FDS6670  [SOIC8]  105.25,43.98 270 top
Q21  FDS6670  [SOIC8]  105.25,37.62 90 bottom
Q22  FDS6670  [SOIC8]  105.25,37.62 270 top
Q23  FDS6670  [SOIC8]  105.25,31.27 90 bottom
Q24  FDS6670  [SOIC8]  105.25,31.27 270 top
Q25  FDS6670  [SOIC8]  14.77,90.33 270 bottom
Q26  FDS6670  [SOIC8]  14.77,90.33 90 top
Q27  FDS6670  [SOIC8]  14.77,96.68 270 bottom
Q28  FDS6670  [SOIC8]  14.77,96.68 90 top
Q29  FDS6670  [SOIC8]  14.77,103.03 270 bottom
Q30  FDS6670  [SOIC8]  14.77,103.03 90 top
Q31  BCW66  [SOT23-BEC]  62.07,53.82 0 top
Q32  BCW66  [SOT23-BEC]  66.52,53.18 180 top
Q33  12MHz  [CRYSTAL-7A]  57.95,105.25 180 top
Q34  IRLR8743  [D-PAK_TO252AA]  32.55,15.4 180 bottom
Q35  BCW66  [SOT23-BEC]  50.96,35.72 270 top
Q36  BSS138  [SOT23]  84.93,65.56 180 top
Q37  BSS138  [SOT23]  36.04,67.15 270 top
Q38  BSS138  [SOT23]  37.31,37.31 270 top
Q39  BSS138  [SOT23]  83.34,37.94 90 top
Q40  BSS138  [SOT23]  31.91,85.25 270 top
QG1  12MHz  [SM77H]  74.45,32.55 180 top
QG2  12MHz  [SM77H]  102.39,9.68 270 top
R1  10k  [R0805]  84.93,69.06 0 top
R6  0R005 2W  [R2512]  105.25,56.67 180 top
R7  10k  [R0805]  34.45,71.6 270 top
R12  0R005 2W  [R2512]  14.77,56.67 0 top
R13  10k  [R0805]  21.11,25.56 180 top
R18  0R005 2W  [R2512]  14.77,47.15 0 top
R19  10k  [R0805]  95.73,25.88 180 top
R24  0R005 2W  [R2512]  105.25,48.42 180 top
R25  10k  [R0805]  28.73,85.25 90 top
R30  0R005 2W  [R2512]  14.77,85.89 0 top
R43  10k  [R0805]  57.63,37.62 180 top
R44  470  [R0805]  60.17,31.91 180 top
R45  470  [R0805]  60.17,33.81 180 top
R46  1k  [R0805]  69.06,48.1 0 top
R47  10  [R0805]  47.15,45.24 270 top
R48  1k  [R0805]  55.72,45.24 270 top
R49  100k  [R0805]  52.23,50.01 0 top
R50  120  [R0805]  58.26,53.82 180 top
R51  10k  [R0805]  58.26,51.59 0 top
R52  120  [R0805]  113.83,55.09 0 top
R53  10k  [R0805]  66.52,56.36 0 top
R54  10k  [R0805]  55.41,55.72 180 top
R55  470  [R0805]  99.38,108.11 0 top
R56  470  [R0805]  99.38,110.02 0 top
R57  10k  [R0805]  111.28,97.95 180 top
R58  470  [R0805]  50.96,101.12 90 top
R59  470  [R0805]  49.05,101.12 90 top
R60  270  [R0805]  57.31,102.08 0 top
R61  20k 0.1%  [R0805]  67.15,5.88 180 top
R62  27k 0.1%  [R0805]  70.96,5.88 180 top
R63  24k 0.1%  [R0805]  74.77,5.88 0 top
R64  11k 0.1%  [R0805]  78.58,5.88 0 top
R65  10k 0.1%  [R0805]  78.58,7.78 180 top
R66  7k5 0.1%  [R0805]  74.77,7.78 180 top
R67  5k1 0.1%  [R0805]  70.96,7.78 0 top
R68  2k7 0.1%  [R0805]  67.15,7.78 0 top
R69  0R002 3W  [R2512]  59.22,24.92 270 top
R70  10k  [R0805]  25.56,16.67 90 top
R71  10k  [R0805]  25.56,12.86 90 top
R72  27k 0.1%  [R0805]  62.71,28.1 0 top
R73  0R1  [R2512]  59.22,16.67 270 top
R74  100k  [R0805]  50.64,25.88 270 top
R75  316k 0.1%  [R0805]  51.12,31.43 0 top
R76  14k  [R0805]  47.63,31.43 0 top
R77  100k  [R0805]  42.07,30.96 0 top
R78  100k 0.1%  [R0805]  51.12,29.69 180 top
R79  20k 0.1%  [R0805]  62.71,19.84 0 top
R80  100k  [R0805]  44.93,26.2 270 top
R81  0R1  [R2512]  59.22,8.41 90 top
R82  100k  [R0805]  50.64,10 270 top
R83  1k  [R0805]  45.88,35.72 90 top
R84  536k 0.1%  [R0805]  51.12,15.56 0 top
R85  14k  [R0805]  47.63,15.56 0 top
R86  100k  [R0805]  42.07,15.08 0 top
R87  10k  [R0805]  47.78,35.72 90 top
R88  100k 0.1%  [R0805]  51.12,13.81 180 top
R89  20k 0.1%  [R0805]  62.71,11.59 0 top
R90  100k  [R0805]  44.93,10.32 270 top
R91  10  [R0805]  80.17,15.4 270 top
R92  10k  [R0805]  102.39,16.35 0 top
R93  470  [R0805]  89.75,3.33 0 top
R94  1k  [R0805]  88.11,23.97 270 top
RESET  BUTTON4  [BUTTON4]  113.83,102.39 45 top
RN1  4k7  [CAY16]  116.36,78.58 180 top
RN2  100  [CAY16]  116.36,75.41 180 top
RN3  4k7  [CAY16]  4.61,77.31 0 top
RN4  100  [CAY16]  4.61,80.49 0 top
RN5  4k7  [CAY16]  11.91,19.84 90 top
RN6  100  [CAY16]  8.73,19.84 90 top
RN7  4k7  [CAY16]  109.38,20.16 90 top
RN8  100  [CAY16]  106.2,20.16 90 top
RN9  4k7  [CAY16]  14.77,107.79 90 top
RN10  100  [CAY16]  11.59,107.79 90 top
RN12  0  [CAY16]  40.8,45.24 270 top
RN13  0  [CAY16]  95.41,52.55 90 top
RN15  10  [CAY16]  85.89,90.97 270 top
RN16  10k  [CAY16]  85.89,109.06 90 top
RN17  470  [CAY16]  85.89,104.3 270 top
RN18  470  [CAY16]  85.89,94.78 270 top
RN19  10k  [CAY16]  85.89,99.54 270 top
RN20  1k  [CAY16]  71.28,10.64 0 top
RN21  100  [CAY16]  83.66,8.73 270 top
RN22  100  [CAY16]  83.66,14.77 270 top
RN23  1k  [CAY16]  69.22,20.96 0 top
RN24  100  [CAY16]  100.17,3.34 90 top
RX  gr  [CHIP-LED0805]  103.03,110.02 90 top
SJ1  [SJ]  50.64,28.42 270 bottom
SJ2  [SJ]  50.64,12.54 270 bottom
SW1  MFP106D  [SW-KNITTER]  9.05,12.86 0 top
TX  rd  [CHIP-LED0805]  103.03,108.11 90 top
USB1  USB-BMINI  [USB-BMINI]  110.02,104.94 315 bottom
WF1  NRFL01MOD  [NRF24L01MOD]  38.26,108.11 0 bottom

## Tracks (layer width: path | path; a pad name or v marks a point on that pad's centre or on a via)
3V3OUT
  Top 0.254: IC15.17 112.62,94.53 114.14,96.05 C62.1
+3V3  (via drill 0.3, 0.81)
  Top 0.203: IC14.1 58.78,60.68 58.9,60.8 60.48,60.8 | 60.48,60.8 62.7,60.8 C53.1 | IC14.14 60.5,60.79 60.48,60.8
  Top 0.254: L2.P$1 42.07,25.56 | 42.07,25.56 C87.1 42.07,26.2 | IC19.1 45.56,24.61 R80.2 44.61,25.24 44.29,25.56 42.07,25.56 | v46.52,90.97 C74.1 47.91,91.09 IC16.39 | v46.52,84.61 v46.52,84.62 C73.1 47.81,84.59 IC16.52 | v45.88,78.9 C72.1 47.84,79.59 IC16.62 | v46.52,72.23 C71.1 48.1,72.23 49.69,73.82 49.69,74.14 50.15,74.59 IC16.72 | v59.53,67.47 C70.1 58.5,69.77 IC16.84 | v65.25,67.79 C69.1 64,70.3 IC16.95 | v70.33,67.79 70.33,68.74 C68.1 70.5,69.19 IC16.108 | v78.58,80.81 v78.58,80.8 C67.1 77.11,80.59 IC16.121 | v77.31,86.2 C66.1 75.44,85.59 IC16.131 | v77,92.87 v76.99,92.87 C65.1 74.95,92.09 IC16.144 IC16.143 | v53.82,99.86 v53.82,99.85 C82.1 C81.1 54.14,96.36 54.14,96.05 54.5,95.67 IC16.33 IC16.32 55,92.55 56,92.55 IC16.30 | v61.44,99.22 C75.1 62.5,96.89 IC16.17 | R59.2 R58.2 51.12,102.08 52.07,101.12 v52.55,101.12 | v66.2,96.68 C78.1 68,96.58 IC16.6 | IC8.4 66.44,33.58 C43.1 68.03,34.38 | 68.03,34.38 IC8.6 | 68.03,34.38 C43.1 v68.11,33.18 | R91.1 v80.17,17.94 | IC25.4 93.11,4.69 C96.1 | IC25.6 94.7,3.59 C96.1 | C96.1 94.45,2.07 94.46,2.06 93.82,1.43 89.69,1.43 v89.38,1.75 90.7,3.07 R93.2 | 91.92,25.08 L4.1 | 91.92,25.08 | QG1.4 77,30.66 v77,31.91 | LED1.A 55.09,31.91 v54.14,32.86 55.09,33.81 LED2.A | IC13.16 C58.1 51.91,63.03 C59.+ v51.91,59.85 | IC13.16 IC13.15 | IC13.16 IC13.1 | v65.88,63.34 67.15,63.34 C54.+ 67.15,62.39 65.25,60.48 C53.1 | R47.1 v47.15,47.47 | C57.1 39.85,110.65 WF1.2 | C76.+ v77.79,102.71 | 76.68,71.28 C50.1 | IC11.14 38.22,88.38 37.62,87.79 36.67,87.79 C52.1 v36.35,89.06 | IC12.14 39.8,98.54 39.21,97.95 C51.1 v37.94,99.22 | v55.41,37.62 R43.2 | v67.95,51.12 67.95,50.02 L1.1 | 84.82,98.74 v84.14,98.74
  Top 0.254: RN19.4 84.82,98.74 | v85.09,111.13 85.21,111.01 RN16.5 RN16.6 RN16.7 | v112.56,83.98 C60.1 113.82,86.52 118.11,86.52 118.59,86.52 118.91,86.84 118.91,88.9 118.48,89.33 IC15.4 | 105.03,109.06 RX.A | TX.A 105.03,109.06 | 105.03,109.06 v105.25,109.06 | RN19.3 84.82,98.74 | R92.2 v104.62,16.35 | QG2.4 v104.62,10.64 | R75.2 52.39,30.96 v53.34,30.96 | IC10.14 78.22,72.82 76.68,71.28 | 76.68,71.28 v77.63,71.28 | 91.92,25.08 91.92,24.92 93.5,23.34 93.5,22.86 96.68,19.69 v96.68,17.62
  Top 0.406: IC28.3 C101.1 24.29,86.52 v25.88,86.52 | IC6.3 C1.1 24.93,57.31 v25.88,57.31 | IC7.3 C40.1 24.93,49.05 v25.88,49.05 | C100.1 IC26.3 | C100.1 | C100.1 95.09,54.77 v94.14,54.77 | IC27.3 C41.1 95.09,47.78 v94.14,47.78
  Top 0.61: 42.07,26.2 v40.16,26.2 | BD.3 4.61,63.03 7.78,59.85 7.78,54.77 10.64,51.91 24.92,51.91 v25.88,52.87
  Supply 0.406: v25.88,86.52 25.24,87.47
  Bottom 0.254: v89.38,1.75 89.06,2.06 v89.06,5.88
  Bottom 1.626: v81.12,26.2 v89.69,17.62
  pour Top (no thermals): 40.16,22.38 44.61,22.38 46.83,24.61 45.56,25.88 40.8,25.88 40.8,24.92 40.16,24.29
  pour Supply: 47.78,21.11 30.01,21.11 24.92,26.2 24.92,115.73 42.07,115.73 54.77,128.43 94.78,128.43 119.54,103.67 119.54,77.63 97.31,77.63 97.31,26.2 96.68,25.56 64.93,25.56 62.39,28.1 54.77,28.1
  pour Supply: 71.28,17.94 116.05,17.94 116.05,14.77 104.94,3.65 65.25,3.65 65.56,12.23
+3V3-A
  Top 0.254: IC25.23 91.5,14.7 91.12,15.08 88.74,15.08 87.31,16.51 86.36,16.51 86.2,16.35 86.2,15.4 85.97,15.16 CN12.2 RN22.7
+3V3-LOW
  Top 0.254: 50.96,24.61 R74.2 | 50.33,24.61 50.96,24.61 | 50.33,24.61 50.33,22.38 C85.1 49.05,22.38 48.28,23.16 IC19.4 | 50.33,24.61 50.33,24.92 50.96,24.61 | 58.58,14.13 58.9,13.81 R73.2 59.53,14.13 61.75,14.13 61.75,15.08 IC20.4
  Top 0.813: 58.58,14.13 56.67,16.04 56.67,22.07 54.14,24.61 50.96,24.61
  pour Top (no thermals): 50.96,21.11 50.96,23.66 51.28,23.97 51.28,25.56 50.01,25.56 50.01,24.29 49.37,23.66 48.42,23.66 48.42,21.11
+3V3-SHUNT
  Top 0.254: IC20.1 R79.2 63.66,21.11 64.93,22.38 68.42,22.38 68.82,21.99 RN23.7
+5V  (via drill 0.3)
  Top 0.254: 42.07,9.68 L3.P$1 | 42.07,9.68 C92.1 42.07,10.32 | 42.07,9.68 44.61,9.68 R90.2 45.56,8.73 IC21.1 | IC17.5 v63.66,22.38 IC17.5 | IC20.5 63.66,15.4 v63.66,14.13 | IC22.5 63.66,7.14 v64.61,7.14 | v6.83,82.87 3.81,82.87 | C15.1 3.81,83.51 3.81,82.87 | M5.1 4.92,105.89 6.2,107.16 C39.1 | RN1.8 RN1.7 RN1.6 RN1.5 114.78,77.52 v114.78,77 | RN7.8 RN7.7 RN7.6 RN7.5 108.32,21.75 v107.79,21.75 105.25,24.29 v103.03,24.29 C31.1 | RN5.8 RN5.7 RN5.6 RN5.5 10.84,21.43 v10.32,21.43 | RN3.6 RN3.7 RN3.8 2.98,77.99 2.54,78.42 2.54,82.23 3.18,82.87 3.81,82.87 | RN9.8 RN9.7 RN9.6 RN9.5 13.7,109.38 v13.18,109.38 | R84.2 52.55,15.08 v53.34,15.08 | C23.1 v3.34,23.34 | v116.05,70.96 C7.1
  Top 0.406: 115.42,52.23 115.42,54.45 R52.2
  Top 0.61: v40.16,10.32 42.07,10.32 | C16.1 4.92,44.61 ENC2.1 | C24.1 ENC3.1 | C8.1 115.42,52.23 ENC1.1 | C32.1 115.42,36.99 ENC4.1 | IC17.5
  Supply 0.254: v13.18,109.38 5.88,109.38 3.34,106.84 M5.1 | 1.11,82.87 v6.83,82.87 | 1.11,21.43 v10.32,21.43 | 1.11,23.34 v3.34,23.34
  Supply 0.406: 118.91,23.02 109.06,23.02 v107.79,21.75 | 118.91,70.96 v116.05,70.96 | v114.78,77 114.78,76.68 116.05,75.41 117.95,75.41 118.91,74.45
  Supply 0.61: 1.11,29.37 ENC3.1 | 1.11,44.61 ENC2.1 | 118.91,36.99 ENC4.1 | 118.91,52.23 ENC1.1 | v53.34,15.08 54.45,13.97 54.45,7.78 53.18,6.51 53.18,4.29
  Supply 0.813: 118.91,74.45 118.91,70.96 118.91,52.23 118.91,36.99 118.91,23.02 118.91,15.4 111.92,8.41 101.44,8.41 96.36,3.34 83.34,3.34 82.39,4.29 63.66,4.29 | M5.1 1.11,103.67 1.11,82.87 1.11,44.61 1.11,29.37 1.11,23.34 1.11,21.43 1.11,15.72 2.06,14.77 6.51,14.77 7.14,14.13 7.14,11.59 7.78,10.95 11.59,10.95 15.4,7.14 15.4,1.43 28.1,1.43 30.96,4.29 40.16,4.29 | IC22.5 v63.66,14.13 | 63.66,4.29 IC22.5 | IC22.5 64.58,7.11 v64.61,7.14 | 40.16,4.29 53.18,4.29 63.66,4.29 | 40.16,4.29 v40.16,10.32
  Bottom 0.254: v3.34,23.34 5.18,23.34 M3.1 | M1.1 112.64,72 113.19,71.92 115.09,71.92 v116.05,70.96 | M4.1 104.3,23.56 104.3,24.29 v103.03,24.29 | v6.83,82.87 6.83,82.14 M2.1
  Bottom 0.406: ENC1.1 116.36,52.55
  Bottom 0.61: v63.66,14.13 v63.66,22.38 68.74,27.47 EXTPWR.2
  pour Top (no thermals): 40.16,6.51 44.61,6.51 46.83,8.73 45.56,10 40.8,10 40.8,9.05 40.16,8.41
+5V-A
  Top 0.254: 90.7,13.81 IC25.24 90.7,13.71 90.49,13.5 88.11,13.5 87.63,13.02 86.36,13.02 86.2,13.18 86.2,14.13 85.97,14.36 CN12.3 RN22.6
+5V-LOW
  Top 0.254: 50.33,8.73 R82.2 | C90.1 50.33,7.14 | C90.1 50.33,6.51 50.33,7.14 | 50.33,7.14 50.33,8.73 | 50.33,8.73 50.64,8.73 | R81.1 58.9,5.56 58.58,5.88 | R81.1 59.53,5.88 | IC22.4 61.75,7.14 61.75,5.56 59.22,5.56 R81.1 | IC21.4 48.28,7.28 49.05,6.51 C90.1
  Top 0.813: 50.64,8.73 54.45,8.73 57.31,5.88 58.58,5.88
  pour Top (no thermals): 50.96,5.24 50.96,7.78 51.28,8.1 51.28,9.68 50.01,9.68 50.01,8.41 49.37,7.78 48.42,7.78 48.42,5.24
+5V-SHUNT
  Top 0.254: IC22.1 | IC22.1 63.66,9.68 | IC22.1 R89.2 64.93,12.86 64.93,18.57 67.99,21.63 RN23.8
ACC-CS  (via drill 0.3)
  Top 0.254: IC14.8 60.5,57.3 v61.12,56.67 | IC16.79 56,74.1 v56.36,74.45
  Bottom 0.254: v56.36,74.45 62.07,68.74 62.07,66.52 63.98,64.61 63.98,62.07 61.44,59.53 61.44,56.99 v61.12,56.67
BAT+
  Top 0.406: BAT1+.P$1 59.85,3.97 61.75,3.97 63.34,5.56 65.89,5.56 R61.2
  pour Bottom (no thermals): 31.27,3.34 31.91,3.97 57.94,3.97 59.22,2.7 59.22,1.43 58.58,0.79 31.27,0.79
BAT-FS  (via drill 0.3)
  Top 0.61: 22.38,16.04 20.8,16.04 19.84,16.99 IC18.8 | 22.38,16.04 IC18.6 | 22.38,16.04 23.5,16.04 24.92,17.46 25.4,17.46 R70.2 v27.47,17.62
  Bottom 0.61: 30.8,17.15 32.55,15.4 Q34.4 | 30.8,17.15 30.64,17.3 | v27.47,17.62 28.1,16.99 30.32,16.99 30.48,17.15 30.8,17.15
  pour Bottom (no thermals): 32.23,25.56 31.59,24.92 31.27,24.61 31.27,18.57 30.01,17.3 30.01,15.4 35.09,15.4 35.09,17.3 34.13,18.26 33.81,18.57 33.81,24.61 32.86,25.56
  pour Bottom (no thermals): 36.04,5.88 36.04,9.05 35.09,10 32.23,10 33.5,8.73 33.5,5.88
BD-AOUT  (via drill 0.3)
  Top 0.254: IC8.28 61.2,39.93 v61.12,39.85 | v59.22,44.29 C48.2 R48.2
  Bottom 0.254: v61.12,39.85 61.12,41.44 59.37,43.18 | 59.37,43.18 | 59.37,43.18 59.22,43.34 v59.22,44.29
BD-IRQ  (via drill 0.3)
  Top 0.254: IC8.2 64.83,38.16 v64.93,38.26 | IC16.55 53.75,83.09 v53.82,83.03
  Bottom 0.254: v64.93,38.26 63.66,38.26 62.39,39.53 62.39,44.29 58.26,48.42 58.26,53.5 53.18,58.58 51.28,58.58 50.01,59.85 50.01,68.74 50.96,69.69 50.96,80.17 v53.82,83.03
BUZZ  (via drill 0.3)
  Top 0.254: IC16.140 71.2,90.09 70.64,90.65 69.38,90.65 65.56,86.84 65.56,83.34 58.58,76.36 58.58,74.77 v58.26,74.45 | v65.56,57.63 R53.1
  Bottom 0.254: v58.26,74.45 58.26,73.5 62.55,69.22 62.55,66.99 64.61,64.93 64.61,58.58 v65.56,57.63
C1-A
  Top 0.254: IC25.25 89.16,12.54 86.04,12.54 85.53,13.06 CN12.4 RN22.5
C2-A
  Top 0.254: IC25.26 86.77,11.68 85.53,10.44 CN11.1 RN21.8
C3-A
  Top 0.254: IC25.27 86.77,10.89 86.2,10.32 86.2,9.37 85.97,9.13 CN11.2 RN21.7
C4-A
  Top 0.254: IC25.28 88.67,10.09 87.79,9.21 87.79,7.46 87.31,6.99 86.36,6.99 86.2,7.14 86.2,8.1 85.97,8.33 CN11.3 RN21.6
CELL1
  Top 0.254: 79.22,5.56 R64.2
  Top 0.406: BAT2#.1 79.22,3.65 79.22,5.56
CELL1-ADC
  Top 0.254: RN20.4 72.6,9.84 74.93,9.84 75.72,9.05 76.52,9.05 77.63,7.94 R65.2 R64.1
CELL2
  Top 0.254: 75.41,5.56 R63.2
  Top 0.406: BAT2+.P$1 75.41,3.65 75.41,5.56
  pour Bottom (no thermals): 64.3,2.7 64.93,3.34 74.45,3.34 75.09,2.7 75.09,1.43 74.45,0.79 64.93,0.79 64.3,1.43
  pour Top (no thermals): 64.3,2.7 64.93,3.34 74.45,3.34 75.09,2.7 75.09,1.43 74.45,0.79 64.93,0.79 64.3,1.43
CELL2-ADC
  Top 0.254: RN20.3 71.68,9.44 72.07,9.05 72.71,9.05 73.82,7.94 R66.2 R63.1
CELL3
  Top 0.406: BAT1#.1 63.98,4.29 68.74,4.29 70.01,5.56 R62.2
CELL3-ADC
  Top 0.254: RN20.2 70.88,9.29 71.91,8.26 R67.2 R62.1
CELL4-ADC
  Top 0.254: RN20.1 69.97,9.96 68.1,8.09 R68.2 R61.1
EN  (via drill 0.3)
  Top 0.254: R82.1 | IC21.5 48.78,9.41 50.01,10.64 50.33,10.64 R82.1 | v52.23,34.45 52.23,35.55 Q35.C | R82.1 51.12,10.48 52.55,10.48 C91.1 53.03,10 v55.41,10
  Bottom 0.254: v55.41,10 58.26,7.14 60.17,7.14 61.12,8.1 61.12,25.88 58.9,28.1 57.79,28.1 52.23,33.66 v52.23,34.45
EN5V  (via drill 0.3)
  Top 0.254: R83.1 v44.61,34.77 | v48.1,66.83 50.01,66.83 53.01,69.83 IC16.73
  Bottom 0.254: v48.1,66.83 45.88,64.61 45.88,36.04 v44.61,34.77
ENC1-A  (via drill 0.3)
  Top 0.254: ENC1.2 118.59,51.59 118.59,64.45 112.08,70.96 112.08,77 110.17,78.9 107.32,78.9 105.41,77 84.3,77 v83.98,76.68 | v63.66,77 64.5,76.15 IC16.96
  Bottom 0.254: v63.66,77 68.42,72.23 81.44,72.23 83.03,73.82 83.03,75.72 v83.98,76.68
ENC1-B  (via drill 0.3)
  Top 0.254: ENC1.4 119.22,47.15 119.22,64.61 112.56,71.28 112.56,77.31 110.33,79.53 107.16,79.53 105.25,77.63 v83.98,77.63 | v64.61,77 65,76.6 IC16.97
  Bottom 0.254: v64.61,77 68.74,72.87 81.12,72.87 82.39,74.14 82.39,76.04 v83.98,77.63
ENC2-A  (via drill 0.3)
  Top 0.152: v52.55,96.05 53.18,95.41 53.5,95.41 54,94.91 IC16.34
  Bottom 0.254: v52.55,96.05 51.91,96.68 43.98,96.68 39.21,91.92 39.21,90.33 29.69,80.81 12.07,80.81 11.43,80.81 7.94,84.3 6.67,84.3 6.03,83.66 2.06,83.66 0.79,82.39 0.79,48.1 1.75,47.15 ENC2.2
ENC2-B  (via drill 0.3)
  Top 0.152: v52.55,95.09 53.18,95.09 53.51,94.77 IC16.35
  Bottom 0.254: v52.55,95.09 51.59,96.05 44.29,96.05 40.16,91.92 40.16,90.33 31.27,81.44 30.32,80.49 30.01,80.17 11.27,80.17 7.78,83.66 6.67,83.66 6.03,83.03 2.06,83.03 1.43,82.39 1.43,52.55 1.75,52.23 ENC2.4
ENC3-A
  Top 0.254: ENC3.2 0.79,31.91 0.79,84.93 1.43,85.57 6.67,85.57 12.7,79.53 43.02,79.53 45.24,81.76 48.42,81.76 49.58,80.59 IC16.60
ENC3-B
  Top 0.254: ENC3.4 1.43,36.99 1.43,84.61 1.91,85.09 6.35,85.09 12.54,78.9 43.02,78.9 43.98,77.95 48.42,77.95 49.07,78.59 IC16.64
ENC4-A  (via drill 0.3)
  Top 0.254: IC16.136 73.81,88.09 74.77,89.06 83.03,89.06 86.2,85.89 v86.36,85.89
  Bottom 0.254: ENC4.2 118.59,36.35 118.59,86.52 117.95,87.16 106.84,87.16 105.57,85.89 v86.36,85.89
ENC4-B  (via drill 0.3)
  Top 0.254: IC16.137 73.67,88.59 74.77,89.69 83.19,89.69 86.36,86.52 v87,86.52
  Bottom 0.254: ENC4.4 119.22,31.91 119.22,86.84 118.27,87.79 106.52,87.79 105.25,86.52 v87,86.52
EXT1  (via drill 0.3)
  Top 0.254: IC16.7 67.5,92.91 v66.83,92.23
  Bottom 0.254: v66.83,92.23 66.2,91.6 66.2,90.97 66.52,90.65 67.15,90.65 67.47,90.97 67.47,91.28 73.19,97 73.19,101.76 68.11,106.84 62.39,106.84 EXT.1
EXT2  (via drill 0.3)
  Top 0.254: IC16.139 70.75,89.59 v70.33,90.01
  Bottom 0.254: v70.33,90.01 70.33,90.33 75.72,95.73 75.72,103.03 69.38,109.38 68.11,109.38 67.47,110.02 67.47,111.28 66.83,111.92 59.85,111.92 EXT.2
EXT3  (via drill 0.3)
  Top 0.254: IC16.123 69.86,81.59 69.38,82.08 v69.38,89.69
  Bottom 0.254: v69.38,89.69 69.38,90.33 75.09,96.05 75.09,102.71 70.64,107.16 69.69,108.11 69.06,108.75 66.83,108.75 66.2,109.38 EXT.7
FLT1
  Top 0.254: IC1.8 87.47,66.83 86.52,67.79 85.57,67.79 | 85.57,67.79 85.57,69.06 R1.2 | Q36.1 85.57,66.98 85.57,67.79
FLT2
  Top 0.254: Q37.1
  Top 0.406: IC2.8 33.5,68.11 Q37.1 | R7.2 34.77,70.33 34.77,68.74 34.77,68.27 Q37.1
FLT3
  Top 0.254: IC3.8 33.02,36.99 34.77,36.99 36.03,38.26 Q38.1
  Top 0.406: R13.2 20.16,25.88 21.11,26.83 25.24,26.83 29.37,30.96 29.37,36.04 30.32,36.99 IC3.8
FLT4  (via drill 0.3)
  Top 0.254: Q39.1 IC4.8
  Top 0.406: v89.85,36.99 IC4.8 | v93.5,26.51 94.14,25.88 R19.2
  Bottom 0.406: v89.85,36.99 89.85,35.09 89.85,28.26 90.97,27.15 92.87,27.15 v93.5,26.51
FLT5
  Top 0.254: IC5.8 29.37,97.31 28.73,96.68 28.73,88.42 R25.2
  Top 0.406: R25.2 Q40.1
GND  (via drill 0.3, 0.81)
  Top 0.203: IC14.5 58.95,58 59.85,58.9 60.46,58.9 60.46,59.5 | 60.46,59.5 IC14.12 | 60.46,59.5 60.48,59.48 60.48,58.9 60.88,58.5 IC14.10 63.27,58.5 C53.2
  Top 0.254: 41.12,29.37 40.8,28.73 41.44,29.05 41.75,28.73 C87.2 44.74,28.87 C88.2 | C85.2 52.87,22.07 53.82,21.11 v54.45,20.8 54.45,19.21 D23.A | C90.2 52.87,6.19 53.82,5.24 v54.45,5.24 54.45,3.34 D24.A | 41.12,12.86 42.07,12.86 C92.2 44.74,12.99 C93.2 | R86.1 | v62.71,15.4 IC20.2 62.71,18.89 62.08,19.52 61.76,19.52 R79.1 | v62.71,8.41 IC22.2 62.71,10.64 R89.1 | C94.2 v78.27,17.94 78.27,18.57 75.25,21.59 74.77,21.59 | IC23.11 68.42,16.35 74.45,16.35 | 74.45,16.35 75.09,16.35 | 75.72,16.35 C94.2 | C94.2 | 74.45,16.35 IC24.11 | 75.72,16.35 IC24.9 | 75.09,16.35 IC24.10 | 75.09,16.35 75.72,16.35 | v8.41,78.58 8.41,82.39 6.83,83.98 C15.2 | C82.2 C81.2 55.5,96.47 IC16.31 | C82.2 v55.72,99.85 v55.72,99.86 | v77,90.97 v76.99,90.97 C65.2 75.41,90.97 73.54,89.09 IC16.138 | v77.31,84.3 C66.2 75.25,85.09 IC16.130 | v78.58,78.9 C67.2 76.12,80.09 IC16.120 | v46.52,92.87 C74.2 49.06,91.59 IC16.38 | v46.52,86.52 C73.2 47.86,86.59 IC16.48 52.47,86.59 52.55,86.52 52.55,85.25 52.39,85.09 IC16.51 | v45.88,80.81 v45.88,80.8 C72.2 47.86,80.09 IC16.61 | C71.2 v46.52,74.14 46.2,74.14 45.25,73.19 C63.2 | v57.63,67.47 C70.2 58,69.43 IC16.83 | v63.34,67.79 C69.2 63.5,69.22 IC16.94 | v69.06,67.79 69.06,68.74 C68.2 68.74,69.38 70.01,70.64 70.01,71.28 70,71.28 IC16.107 | v63.34,99.22 C75.2 63,97.61 IC16.16 | C78.2 v68.11,99.86 68.11,101.44 69.38,102.71 C76.- | C80.2 v53.98,107.32 | C79.2 61.75,106.52 61.6,106.52 v60.8,107.32 | C77.2 57.63,98.58 C82.2 | R87.1 Q35.E 50.01,34.62 v50.01,33.66 | IC8.5 67.23,35.95 66.83,36.35 65.88,36.35 65.64,36.11 IC8.3 65.64,33.88 C43.2 v63.66,33.18 | IC8.21 66.44,44.7 C46.2 64.3,44.93 61.6,44.93 60.8,45.72 D21.2
  Top 0.254: IC25.5 93.91,6.11 93.5,6.51 92.55,6.51 92.31,6.26 IC25.3 92.31,3.59 C96.2 v92.56,2.07 v92.55,2.06 | C99.2 D25.2 85.16,18.89 C98.- 84.06,18.89 v83.03,18.89 | C97.2 v90.01,26.04 | QG1.2 71.92,34.44 v71.92,33.18 | IC25.21 93.11,15 92.55,15.55 C99.2 | C99.2 92.87,19.21 | C64.2 72.55,67.79 v71.28,67.79 | IC13.8 61.44,65.24 61.44,65.25 61.12,65.56 60.97,65.56 | 59.03,65.56 58.89,65.56 IC13.13 55.77,64.97 C58.2 51.91,64.93 51.91,65.56 | 59.03,65.56 IC13.12 | 59.03,65.56 59.67,65.56 | 59.67,65.56 IC13.11 | 59.67,65.56 60.33,65.56 | 60.33,65.56 IC13.10 | 60.33,65.56 60.97,65.56 | 60.97,65.56 IC13.9 | C59.- 51.91,65.56 | 51.91,65.56 v53.18,65.56 | C53.2 63.34,58.26 67.15,58.26 67.15,58.9 | 67.15,58.9 v65.88,58.9 | 67.15,58.9 C54.- | v53.18,60.17 C55.2 | R54.1 56.36,56.04 v57.63,56.04 | IC9.3 IC9.2 50.33,45.24 49.38,46.2 C47.2 v49.05,47.47 | v62.71,23.66 IC17.2 62.71,27.15 R72.1 | IC15.18 111.6,93.88 111.6,91.92 | IC15.26 111.6,88.67 111.6,89.33 | 111.6,89.33 IC15.25 | 111.6,89.33 111.6,91.28 | 111.6,91.28 111.6,91.92 | 111.6,91.92 IC15.21 | IC15.7 114.78,91.28 114.77,91.28 v113.83,91.28 111.6,91.28 | v115.09,104.62 116.69,106.21 RESET.2 | RESET.1 110.57,111.21 v109.38,110.02 | C57.2 39.21,108.11 WF1.1 | IC10.7 82.12,68.22 80.96,69.38 C50.2 | C50.2 76.84,68.9 | IC11.7 42.12,84.57 41.12,85.57 36.99,85.57 C52.2 36.35,84.46 v37.31,83.5 | IC12.7 43.7,94.73 42.7,95.73 38.26,95.73 C51.2 v37.94,94.78 | IC12.2 IC12.1 39.11,94.08 v39.05,94.14 | IC12.12 41.1,98.89 v40.8,98.58 40.45,98.93 IC12.13 | v55.41,39.53 C42.2 | D21.2 60.81,48.02 C45.- | C44.2 v72.23,45.88 | C48.1 v59.22,46.2 | D21.2 60.8,48.74 v62.23,48.74 | 84.82,100.33 v84.14,100.33
  Top 0.254: RN19.2 84.82,100.33 | RN19.1 85.21,100.72 84.82,100.33 | v113.51,99.86 C61.2 R57.1 | C62.2 v116.05,99.38 | C60.2 v109.38,85.25 | CN1.8 CN1.7 CN1.6 CN1.5 114.78,80.69 v114.78,80.17 | CN4.8 CN4.7 CN4.6 CN4.5 111.49,21.75 v110.97,21.75 | CN3.8 CN3.7 CN3.6 CN3.5 14.02,21.43 v13.5,21.43 | CN2.6 CN2.7 CN2.8 2.9,74.81 2.54,74.45 2.54,72.39 v3.34,71.6 | CN5.8 CN5.7 CN5.6 CN5.5 16.88,109.38 v16.35,109.38 | CN10.4 CN10.3 | CN10.3 CN10.2 CN10.1 | v77.15,12.23 77.15,11.39 CN10.3 | CN12.8 CN12.7 CN12.6 | CN12.5 CN12.6 | CN11.5 CN11.6 CN11.7 CN11.8 87.11,10.16 v87.79,10.16 | v87.79,14.45 86.96,14.45 CN12.6 | R65.1 80.01,8.26 v80.81,8.26 | R68.1 v66.2,9.05 | R67.1 v70.01,9.05 | R66.1 75.72,8.1 v74.77,9.05 | CN13.6 CN13.7 CN13.8 72.42,21.59 74.77,21.59 | CN14.7 CN14.6 CN14.5 103.46,2.06 v104.46,2.06 | C95.2 v104.62,14.45 | QG2.2 v100.17,8.73 | CN7.5 CN7.6 44.41,45.24 | 44.41,45.24 v45.24,45.24 | 44.41,45.24 CN7.7 CN7.8 | 44.41,45.24 | R88.1 52.39,13.5 v53.34,13.5 53.34,12.54 C91.2 | C86.2 53.34,28.41 v53.34,29.37 52.39,29.37 R78.1 | v46.36,10.95 IC21.11 v49.21,10.95 | v46.36,26.83 IC19.11 v49.21,26.83 | C39.2 v8.1,110.17 | C23.2 5.55,25.24 v6.83,25.24 | C31.2 105.25,25.56 v106.36,25.56 | CN13.5 74.81,21.63 74.77,21.59 | v77.63,70.01 77.47,69.85 76.36,69.85 C50.2 | Q40.2 30.64,84.13 v30.64,83.19 | Q37.2 34.77,66.2 33.97,66.99 v33.66,66.99 | v37.62,36.04 36.53,36.04 Q38.2 | v91.28,51.59 92.19,51.59 | CN8.5 CN8.6 CN8.7 92.19,51.59 | Q36.2 83.52,66.2 v82.87,66.2 | Q39.2 83.98,39.36 v83.98,40.01 | 92.19,51.59 CN8.8 | v19.84,87.47
  Top 0.406: IC1.12 87.95,61.75 | Q31.E 63.03,52.87 v64.3,52.87 | v18.26,9.68 C83.2 19.84,10 IC18.1 | Q32.E 65.26,53.98 v64.45,53.98 | R71.1 v25.56,10.64 | C7.2 v114.14,70.96 | IC5.9 32.55,98.58 | IC28.1 C101.2 24.76,84.3 v25.88,83.19 | IC6.1 C1.2 24.93,54.77 v25.88,54.77 | IC7.1 C40.2 24.93,46.52 v25.88,46.52 | C100.2 IC26.1 | C100.2 | C100.2 95.09,57.31 v94.14,57.31 | IC27.1 C41.2 95.09,50.33 v94.14,50.33
  Top 0.61: v40.16,28.73 40.8,28.73 | 41.12,29.37 R77.1 | v40.16,12.86 41.12,12.86 R86.1 | C16.2 7.46,49.69 ENC2.3 | C8.2 112.88,47.15 ENC1.3 | C32.2 112.88,31.91 ENC4.3 | C24.2 5.56,27.15 5.56,32.55 3.65,34.45 ENC3.3 | v100.17,58.26 95.09,58.26 92.87,60.48 IC1.13 90.33,60.48 90.33,61.75 | 90.33,61.75 90.33,63.03 | 90.33,63.03 90.33,65.56 IC1.9 | 90.33,63.03 IC1.11 | 90.33,61.75 IC1.12 | v19.84,45.56 24.92,45.56 27.15,43.34 29.37,43.34 | 29.37,43.34 IC3.13 | IC5.13 29.05,103.67 29.05,102.39 | 29.05,102.39 IC5.12 | 29.05,101.12 IC5.11 | 29.05,101.12 29.05,102.39 | 29.05,98.58 IC5.9 | 29.05,98.58 29.05,101.12 | 29.05,98.58 27.78,97.31 27.78,90.33 24.92,87.47 v19.84,87.47 | 29.37,69.38 IC2.9 | 29.37,69.38 29.37,62.71 24.92,58.26 v19.84,58.26 | 29.37,71.92 IC2.11 | 29.37,69.38 29.37,71.92 | 29.37,73.19 IC2.12 | 29.37,71.92 29.37,73.19 | IC2.13 29.37,74.45 29.37,73.19 | IC3.9 29.37,38.26 29.37,40.8 | 29.37,43.34 29.37,42.07 | 29.37,42.07 29.37,40.8 | 29.37,40.8 IC3.11 | 29.37,42.07 IC3.12 | 90.97,35.72 IC4.9 | 90.97,35.72 90.97,42.39 95.41,46.83 v100.17,46.83 | 90.97,33.18 IC4.11 | 90.97,33.18 90.97,35.72 | 90.97,31.91 IC4.12 | 90.97,31.91 90.97,33.18 | IC4.13 90.97,30.64 90.97,31.91
  Bottom 0.254: M2.5 7.83,78 v8.41,78.58 | M3.5 9.32,24.34 8.41,25.24 v6.83,25.24 | M4.5 108.38,24.34 107.16,25.56 v106.36,25.56 | USB1.5 111.96,104.62 112.59,103.98 114.46,103.98 v115.09,104.62 | SJ2.1 50.83,13.5 v53.34,13.5 | SJ1.1 50.83,29.37 v53.34,29.37 | M1.5 114.19,76 114.78,75.41 117,75.41 118.11,74.3 118.11,71.76 116.68,70.33 114.78,70.33 v114.14,70.96
  other vias: 103.03,19.53 28.1,7.78 28.1,6.51 28.1,4.92 29.37,4.92
  pour Top (no thermals): 52.55,17.3 52.55,20.8 52.23,21.11 52.23,23.66 53.82,23.66 53.82,22.38 55.09,21.11 55.09,17.3
  pour Top (no thermals): 52.55,1.43 52.55,4.92 52.23,5.24 52.23,7.78 53.82,7.78 53.82,6.51 55.09,5.24 55.09,1.43
  pour Top (no thermals): 78.9,15.72 77.31,15.72 77,15.4 77,15.08 68.42,15.08 67.79,14.45 67.79,14.13 66.2,14.13 66.2,16.67 67.47,16.67 67.79,16.99 67.79,17.3 69.06,17.3 69.06,16.99 69.38,16.67 73.5,16.67 73.82,16.99 73.82,17.3 77,17.3 77.31,16.99 78.9,16.99
  pour GND (no thermals): 0.16,104.94 8.41,113.19 8.41,21.75 16.04,14.13 16.04,10.95 3.97,10.95 0.16,14.77
  pour GND (no thermals): 9.68,108.11 19.84,108.11 19.84,24.92 24.92,19.84 25.56,20.48 25.56,21.11 47.78,21.11 48.42,20.48 48.42,19.84 48.42,10.95 16.04,10.95 16.04,17.3 9.68,23.66
  pour GND (no thermals): 110.65,60.48 100.49,60.48 100.49,27.47 96.68,23.66 64.3,23.66 61.75,26.2 54.77,26.2 48.42,19.84 48.42,10.95 59.22,10.95 67.47,19.21 103.03,19.21 110.65,26.83
  pour GND (no thermals): 111.92,76.36 119.54,76.36 119.54,14.77 104.94,0.16 59.22,0.16 59.22,10.95 61.12,10.95 68.11,17.94 104.3,17.94 111.92,25.56
  pour GND (no thermals): 25.56,21.11 21.11,25.56 21.11,109.38 9.68,109.38 9.68,114.46 15.4,120.18 104.94,120.18 119.54,105.57 119.54,77.63 110.65,77.63 110.65,61.75 99.22,61.75 99.22,28.1 96.68,25.56 64.93,25.56 62.39,28.1 54.77,28.1 47.78,21.11
  pour GND (no thermals): 5.24,10.95 15.4,0.16 59.22,0.16 59.22,10.95
  pour Bottom (no thermals): 31.27,8.41 27.78,8.41 27.47,8.1 27.47,4.61 27.78,4.29 30.01,4.29 31.59,5.88 31.59,8.41
  pour Top (no thermals): 101.12,76.04 105.25,76.04 105.25,56.36 106.84,54.77 109.38,54.77 109.7,54.45 109.7,53.82 109.06,53.18 105.89,53.18 105.89,54.14 103.98,56.04 103.98,60.17 101.12,60.17 101.12,63.34 103.67,63.34 103.67,66.52 101.12,66.52 101.12,69.69 103.67,69.69 103.67,72.87 101.12,72.87
  pour Top (no thermals): 101.12,30.32 105.25,30.32 105.25,48.74 106.84,50.33 109.38,50.33 109.7,50.64 109.7,51.28 109.06,51.91 105.89,51.91 105.89,50.96 103.98,49.05 103.98,46.2 101.12,46.2 101.12,43.02 103.67,43.02 103.67,39.85 101.12,39.85 101.12,36.67 103.67,36.67 103.67,33.5 101.12,33.5
  pour Top (no thermals): 18.89,27.78 14.77,27.78 14.77,47.47 13.18,49.05 10.64,49.05 10.32,49.37 10.32,50.01 10.95,50.64 14.13,50.64 14.13,49.69 16.04,47.78 16.04,43.66 18.89,43.66 18.89,40.48 16.35,40.48 16.35,37.31 18.89,37.31 18.89,34.13 16.35,34.13 16.35,30.96 18.89,30.96
  pour Top (no thermals): 18.89,74.77 14.77,74.77 14.77,56.36 13.18,54.77 10.64,54.77 10.32,54.45 10.32,53.82 10.95,53.18 14.13,53.18 14.13,54.14 16.04,56.04 16.04,58.9 18.89,58.9 18.89,62.07 16.35,62.07 16.35,65.25 18.89,65.25 18.89,68.42 16.35,68.42 16.35,71.6 18.89,71.6
  pour Top (no thermals): 18.89,103.98 14.77,103.98 14.77,85.57 13.18,83.98 10.64,83.98 10.32,83.66 10.32,83.03 10.95,82.39 14.13,82.39 14.13,83.34 16.04,85.25 16.04,88.11 18.89,88.11 18.89,91.28 16.35,91.28 16.35,94.46 18.89,94.46 18.89,97.63 16.35,97.63 16.35,100.81 18.89,100.81
GYR-CS  (via drill 0.3)
  Top 0.254: IC16.80 56.5,70.81 v56.67,70.64 | IC13.5 63.03,63.03 v63.34,63.34
  Bottom 0.254: v63.34,63.34 62.07,63.34 61.75,63.66 61.75,64.93 60.8,65.88 60.8,68.11 58.26,70.64 v56.67,70.64
HALL-I1  (via drill 0.3)
  Top 0.254: v57.94,92.23 58,92.3 IC16.26 | v81.76,71.6 82.12,71.96 IC10.8
  Bottom 0.254: v57.94,92.23 58.58,91.6 62.07,91.6 63.03,90.65 63.03,76.68 68.11,71.6 73.82,71.6 74.77,70.64 80.81,70.64 v81.76,71.6
HALL-I2  (via drill 0.3)
  Top 0.254: v57.31,91.6 57,91.91 IC16.28 | IC11.8 42.12,90.6 41.44,91.28 v41.12,91.28
  Bottom 0.254: v57.31,91.6 57.31,92.55 55.41,94.46 52.23,94.46 51.28,95.41 44.93,95.41 41.12,91.6 v41.12,91.28
HALL-I3
  Top 0.254: IC16.44 49.23,88.59 48.42,87.79 46.2,87.79 42.7,84.3 42.7,83.34 42.39,83.03 41.75,83.03 41.47,83.31 IC11.6
HALL-I4  (via drill 0.3)
  Top 0.254: v56.99,79.85 56.99,90.65 56.5,91.14 IC16.29 | v69.69,67.15 70.96,67.15 71.6,66.52 76.2,66.52 78.58,68.9 80.81,68.9 81.47,68.23 IC10.6
  Bottom 0.254: v56.99,79.85 56.99,77.95 57.63,77.31 61.44,77.31 63.66,75.09 63.66,73.82 68.11,69.38 68.11,67.79 68.74,67.15 v69.69,67.15
HALL-I5  (via drill 0.3)
  Top 0.254: v57.31,95.41 57.5,95.22 IC16.27 | v44.13,97.31 43.7,97.75 IC12.8
  Bottom 0.254: v57.31,95.41 55.41,97.31 v44.13,97.31
IR-LED  (via drill 0.3)
  Top 0.254: IC8.1 64.03,38.63 v64.3,38.9 | v59.06,50.17 58.58,50.17 57.31,51.43 R51.1
  Bottom 0.254: v64.3,38.9 63.03,40.16 63.03,44.77 60.48,47.31 | 60.48,47.31 | 60.48,47.31 59.06,48.74 v59.06,50.17
JTAG-SRST
  Top 0.254: JTAG.15 91.28,95.09 86.64,95.09 RN18.7
JTAG-TCK
  Top 0.254: JTAG.9 90.89,103.1 RN17.5 86.52,103.06 86.52,100.78 RN19.8
JTAG-TDI  (via drill 0.3)
  Top 0.254: JTAG.5 88.83,104.7 RN17.7 | RN16.3 86.64,109.54 v87.47,109.54
  Bottom 0.254: v87.47,109.54 89.54,109.54 JTAG.5
JTAG-TDO
  Top 0.254: 86.68,97.31 JTAG.13 | 86.68,97.31 86.68,98.22 RN19.5 | RN18.8 86.68,96.09 86.68,97.31
JTAG-TMS  (via drill 0.3)
  Top 0.254: JTAG.7 90.56,103.9 RN17.6 | RN16.2 86.64,108.59 v87.47,108.59
  Bottom 0.254: v87.47,108.59 87.95,108.59 JTAG.7
JTAG-TRST
  Top 0.254: RN17.8 87.08,105.5 JTAG.3 91.35,110.26 RN16.4
KD-CS
  Top 0.254: IC16.132 73.71,86.09 74.77,87.16 83.34,87.16 85.89,84.61 99.54,84.61 103.98,89.06 103.98,90.97 KD.7
KD-RST
  Top 0.254: IC16.135 73.94,87.59 74.77,88.42 82.87,88.42 86.04,85.25 98.27,85.25 KD.9
LED0
  Top 0.254: LED4.C 49.37,95.79 49.37,94.46 50.01,93.82 50.96,93.82 52.55,92.23 52.55,90.97 52.18,90.59 IC16.40
LED1
  Top 0.254: LED3.C 51.06,95.63 52.23,94.46 53.01,94.46 IC16.36
M1-A  (via drill 0.3)
  Top 0.61: v100.17,71.92 100.17,73.5 C4.2 99.86,73.19 IC1.26
  Bottom 0.61: M1.10 M1.11 | v100.17,71.92 Q1.1
  other vias: 108.75,77 108.75,77.95 106.2,75.72 106.2,74.45 106.2,73.19 106.2,71.92 107.79,77 107.79,77.95
  pour Top (no thermals): 105.89,76.04 107.47,77.63 107.47,78.27 109.06,78.27 109.06,71.6 105.89,71.6
  pour Bottom (no thermals): 101.12,74.77 103.98,74.77 103.98,76.04 106.52,76.04 106.52,71.6 101.12,71.6
  pour Bottom (no thermals): 114.14,82.08 114.14,80.81 111.6,80.81 109.06,78.27 109.06,76.68 107.47,76.68 107.47,78.9 110.65,82.08
M1-ADC
  Top 0.254: IC26.2 98.27,56.04 98.58,55.72 98.58,54.77 97.63,53.82 96.16,53.82 RN13.4
M1-AOUT  (via drill 0.3)
  Top 0.254: IC8.24 64.03,42.65 v64.93,41.75 | v72.55,44.29 75.41,44.29 80.17,49.05 81.44,49.05 86.2,49.05 89.38,52.23 91.6,54.45 91.92,54.45 92.84,54.45 CN8.4 RN13.5
  Bottom 0.254: v64.93,41.75 70.64,41.75 72.55,43.66 v72.55,44.29
M1-B  (via drill 0.3)
  Top 0.61: v100.17,66.83 100.17,68.42 C5.2 99.86,68.11 IC1.22
  Bottom 0.61: M1.9 M1.8 | v100.17,66.83 Q3.2
  other vias: 110.02,68.11 110.02,66.83 110.02,65.56 106.2,69.38 106.2,68.11 106.2,66.83 106.2,65.56 110.02,69.38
